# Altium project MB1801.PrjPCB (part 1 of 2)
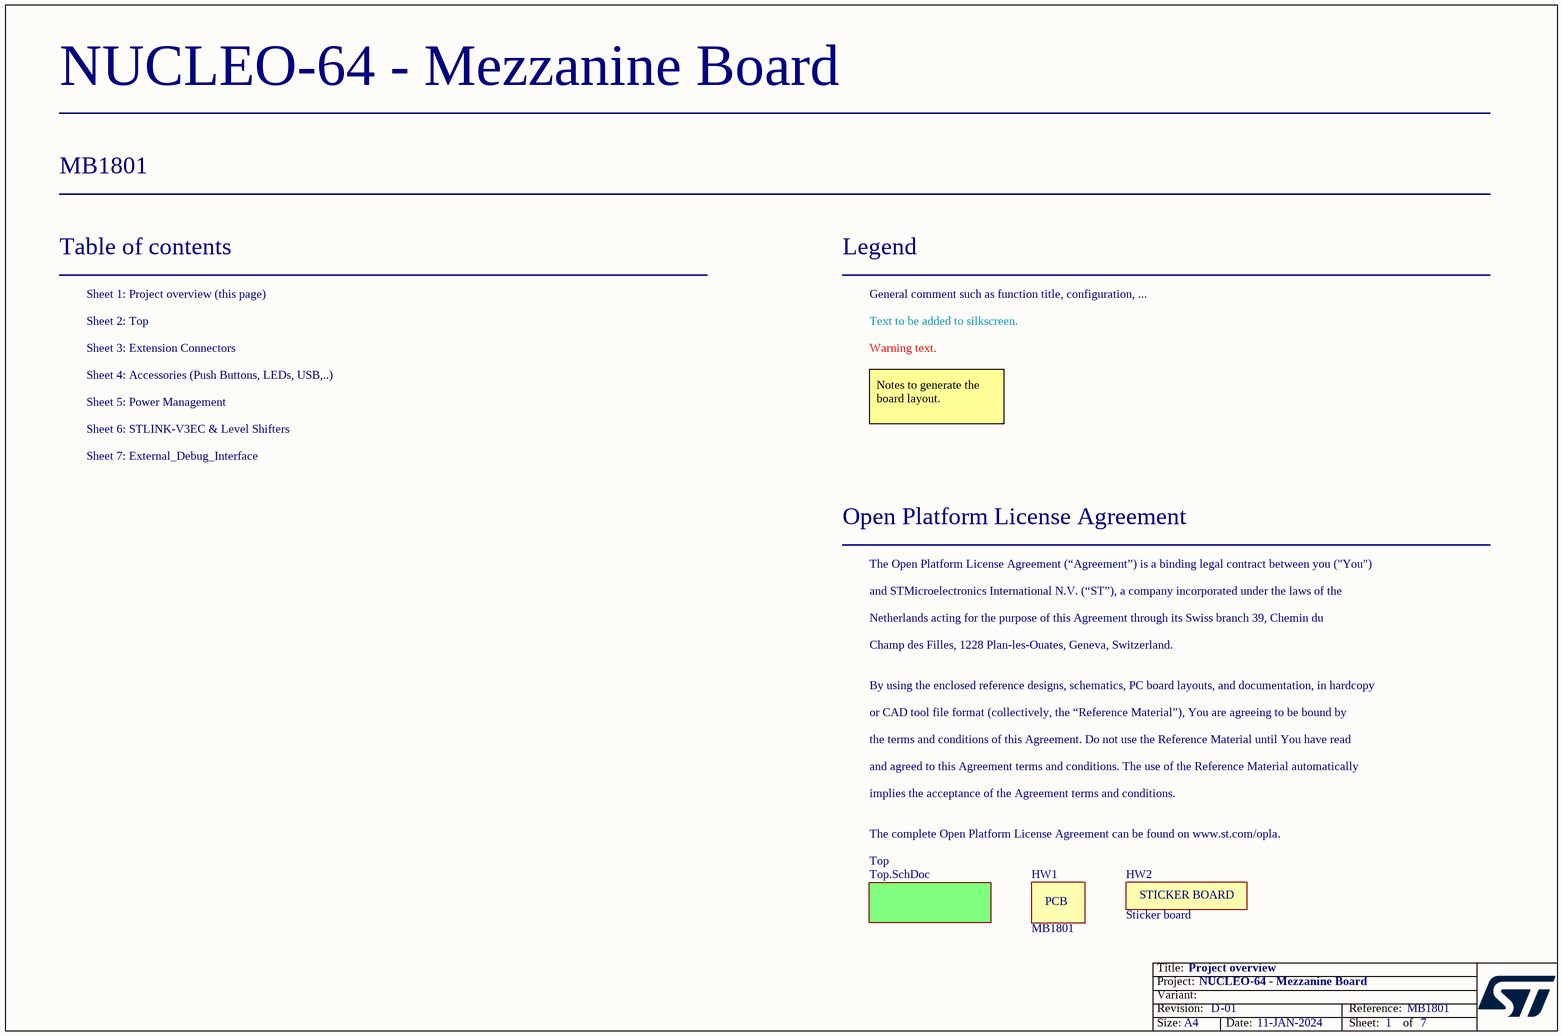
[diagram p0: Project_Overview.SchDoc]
Board_Reference: MB1801; Board_PCB_Revision: D; Board_Name: NUCLEO-64 - Mezzanine Board; Board_Document_Date: 11-JAN-2024; Board_Assembly_Revision: 01
7 sheets, 213 parts. Net scope: flat (ports and power ports of the same name join across sheets).
Board file: MB1801.PcbDoc
Sheets:
  Project_Overview.SchDoc
    Top = Top.SchDoc
      Extension Connectors = Extension_CN.SchDoc
      LEDs & Push Buttons & USB-C Connector = Accessories.SchDoc
      Power Management = Power_Management.SchDoc
      U_STlink-V3EC = STlink-V3EC.SchDoc
      U_External_Debug_Interface = External_Debug_Interface.SchDoc

## Sheet Project_Overview.SchDoc: Project overview
size A4; Date: Not used; ApprovedBy: Not used; CheckedBy: Not used; Author: Not used; CompanyName: STMicroelectronics; DrawnBy: Not used; Engineer: Not used; Organization: Not used; Address1: Not used; Address2: Not used; Address3: Not used; Address4: Not used; DocumentNumber: Not used; Revision: Not used; SheetNumber: 1; SheetTotal: 7

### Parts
HW1  value MB1801  (hidden comment: PCB_MB1801)  (no BOM)
HW2  value Sticker board  [STICKER_BOARD_25X5]  (hidden comment: STICKER_BOARD)  (no BOM)

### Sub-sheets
Top = Top.SchDoc: no entries

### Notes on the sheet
- Table of contents
- Sheet 1: Project overview (this page)
- Legend
- General comment such as function title, configuration, ...
- Sheet 2: Top
- Sheet 3: Extension Connectors
- Sheet 4: Accessories (Push Buttons, LEDs, USB,..)
- Text to be added to silkscreen.
- Warning text.
- Sheet 6: STLINK-V3EC & Level Shifters
- Sheet 5: Power Management
- Notes to generate the board layout.
- Sheet 7: External_Debug_Interface
- Open Platform License Agreement
- The Open Platform License Agreement (“Agreement”) is a binding legal contract between you ("You")
- and STMicroelectronics International N.V. (“ST”), a company incorporated under the laws of the
- Netherlands acting for the purpose of this Agreement through its Swiss branch 39, Chemin du
- Champ des Filles, 1228 Plan-les-Ouates, Geneva, Switzerland.
- By using the enclosed reference designs, schematics, PC board layouts, and documentation, in hardcopy
- or CAD tool file format (collectively, the “Reference Material”), You are agreeing to be bound by
- the terms and conditions of this Agreement. Do not use the Reference Material until You have read
- and agreed to this Agreement terms and conditions. The use of the Reference Material automatically
- implies the acceptance of the Agreement terms and conditions.
- The complete Open Platform License Agreement can be found on www.st.com/opla.

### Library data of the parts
HW1 = MCD-02707: PCB 2L2S of NUCLEO64 for MiniBoard; Part_Preference: Recommended; Manufacturer: EMS; Order_Code_RS: NA
HW2 = MCD-02190: Sticker board 25x5 mm; Part_Type: Misc; Part_Preference: Recommended

## Sheet Top.SchDoc: Top Schematic
size A4; Date: Not used; ApprovedBy: Not used; CheckedBy: Not used; Author: Not used; CompanyName: STMicroelectronics; DrawnBy: Not used; Engineer: Not used; Organization: Not used; Address1: Not used; Address2: Not used; Address3: Not used; Address4: Not used; DocumentNumber: Not used; Revision: Not used; SheetNumber: 2; SheetTotal: 7
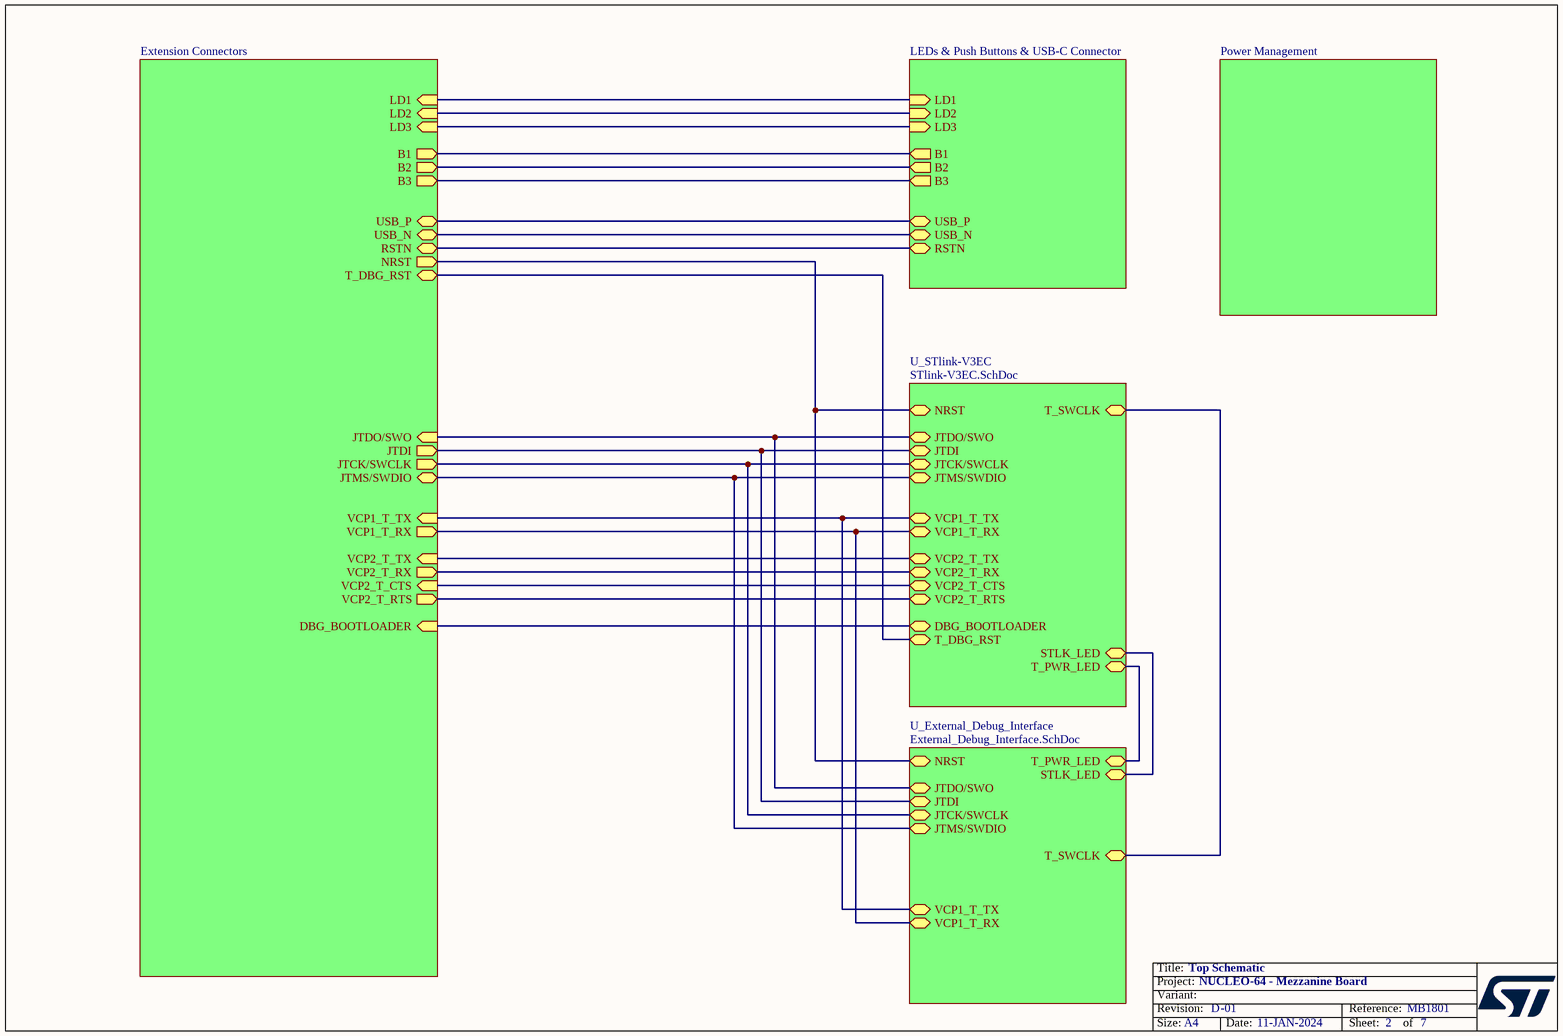
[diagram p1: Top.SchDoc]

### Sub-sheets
Extension Connectors = Extension_CN.SchDoc: JTMS/SWDIO (bidir), USB_P (bidir), USB_N (bidir), NRST (out), LD2 (in), LD3 (in), JTDI (out), B3 (out), B1 (out), JTDO/SWO (in), B2 (out), LD1 (in), DBG_BOOTLOADER (in), VCP1_T_RX (out), VCP2_T_CTS (in), VCP1_T_TX (in), VCP2_T_RX (out), VCP2_T_RTS (out), VCP2_T_TX (in), JTCK/SWCLK (out), T_DBG_RST (bidir), RSTN (bidir)
LEDs & Push Buttons & USB-C Connector = Accessories.SchDoc: LD1 (in), LD2 (in), LD3 (in), B1 (out), B2 (out), B3 (out), USB_P (bidir), USB_N (bidir), RSTN (bidir)
Power Management = Power_Management.SchDoc: no entries
U_External_Debug_Interface = External_Debug_Interface.SchDoc: JTDI (bidir), VCP1_T_TX (bidir), T_SWCLK (bidir), NRST (bidir), VCP1_T_RX (bidir), STLK_LED (bidir), T_PWR_LED (bidir), JTCK/SWCLK (bidir), JTMS/SWDIO (bidir), JTDO/SWO (bidir)
U_STlink-V3EC = STlink-V3EC.SchDoc: JTMS/SWDIO (bidir), JTDI (bidir), JTDO/SWO (bidir), NRST (bidir), DBG_BOOTLOADER (bidir), STLK_LED (bidir), VCP1_T_RX (bidir), VCP1_T_TX (bidir), T_PWR_LED (bidir), VCP2_T_RTS (bidir), VCP2_T_RX (bidir), VCP2_T_TX (bidir), T_SWCLK (bidir), VCP2_T_CTS (bidir), JTCK/SWCLK (bidir), T_DBG_RST (bidir)

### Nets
(unnamed): sheet Extension Connectors/JTMS/SWDIO, sheet U_STlink-V3EC/JTMS/SWDIO, sheet U_External_Debug_Interface/JTMS/SWDIO
(unnamed): sheet Extension Connectors/USB_P, sheet LEDs & Push Buttons & USB-C Connector/USB_P  [a separate net that carries the same name]
(unnamed): sheet Extension Connectors/USB_N, sheet LEDs & Push Buttons & USB-C Connector/USB_N  [a separate net that carries the same name]
(unnamed): sheet Extension Connectors/NRST, sheet U_STlink-V3EC/NRST, sheet U_External_Debug_Interface/NRST  [a separate net that carries the same name]
(unnamed): sheet Extension Connectors/LD2, sheet LEDs & Push Buttons & USB-C Connector/LD2  [a separate net that carries the same name]
(unnamed): sheet Extension Connectors/LD3, sheet LEDs & Push Buttons & USB-C Connector/LD3  [a separate net that carries the same name]
(unnamed): sheet Extension Connectors/JTDI, sheet U_STlink-V3EC/JTDI, sheet U_External_Debug_Interface/JTDI  [a separate net that carries the same name]
(unnamed): sheet Extension Connectors/B3, sheet LEDs & Push Buttons & USB-C Connector/B3  [a separate net that carries the same name]
(unnamed): sheet Extension Connectors/B1, sheet LEDs & Push Buttons & USB-C Connector/B1  [a separate net that carries the same name]
(unnamed): sheet Extension Connectors/JTDO/SWO, sheet U_STlink-V3EC/JTDO/SWO, sheet U_External_Debug_Interface/JTDO/SWO  [a separate net that carries the same name]
(unnamed): sheet Extension Connectors/B2, sheet LEDs & Push Buttons & USB-C Connector/B2  [a separate net that carries the same name]
(unnamed): sheet Extension Connectors/LD1, sheet LEDs & Push Buttons & USB-C Connector/LD1  [a separate net that carries the same name]
(unnamed): sheet Extension Connectors/DBG_BOOTLOADER, sheet U_STlink-V3EC/DBG_BOOTLOADER  [a separate net that carries the same name]
(unnamed): sheet Extension Connectors/VCP1_T_RX, sheet U_STlink-V3EC/VCP1_T_RX, sheet U_External_Debug_Interface/VCP1_T_RX  [a separate net that carries the same name]
(unnamed): sheet Extension Connectors/VCP2_T_CTS, sheet U_STlink-V3EC/VCP2_T_CTS  [a separate net that carries the same name]
(unnamed): sheet Extension Connectors/VCP1_T_TX, sheet U_STlink-V3EC/VCP1_T_TX, sheet U_External_Debug_Interface/VCP1_T_TX  [a separate net that carries the same name]
(unnamed): sheet Extension Connectors/VCP2_T_RX, sheet U_STlink-V3EC/VCP2_T_RX  [a separate net that carries the same name]
(unnamed): sheet Extension Connectors/VCP2_T_RTS, sheet U_STlink-V3EC/VCP2_T_RTS  [a separate net that carries the same name]
(unnamed): sheet Extension Connectors/VCP2_T_TX, sheet U_STlink-V3EC/VCP2_T_TX  [a separate net that carries the same name]
(unnamed): sheet Extension Connectors/JTCK/SWCLK, sheet U_STlink-V3EC/JTCK/SWCLK, sheet U_External_Debug_Interface/JTCK/SWCLK  [a separate net that carries the same name]
(unnamed): sheet Extension Connectors/T_DBG_RST, sheet U_STlink-V3EC/T_DBG_RST  [a separate net that carries the same name]
(unnamed): sheet Extension Connectors/RSTN, sheet LEDs & Push Buttons & USB-C Connector/RSTN  [a separate net that carries the same name]
(unnamed): sheet U_STlink-V3EC/STLK_LED, sheet U_External_Debug_Interface/STLK_LED  [a separate net that carries the same name]
(unnamed): sheet U_STlink-V3EC/T_PWR_LED, sheet U_External_Debug_Interface/T_PWR_LED  [a separate net that carries the same name]
(unnamed): sheet U_STlink-V3EC/T_SWCLK, sheet U_External_Debug_Interface/T_SWCLK  [a separate net that carries the same name]

## Sheet Extension_CN.SchDoc: Extension Connectors
size A4; Date: Not used; ApprovedBy: Not used; CheckedBy: Not used; Author: Not used; CompanyName: STMicroelectronics; DrawnBy: Not used; Engineer: Not used; Organization: Not used; Address1: Not used; Address2: Not used; Address3: Not used; Address4: Not used; DocumentNumber: Not used; Revision: Not used; SheetNumber: 3; SheetTotal: 7
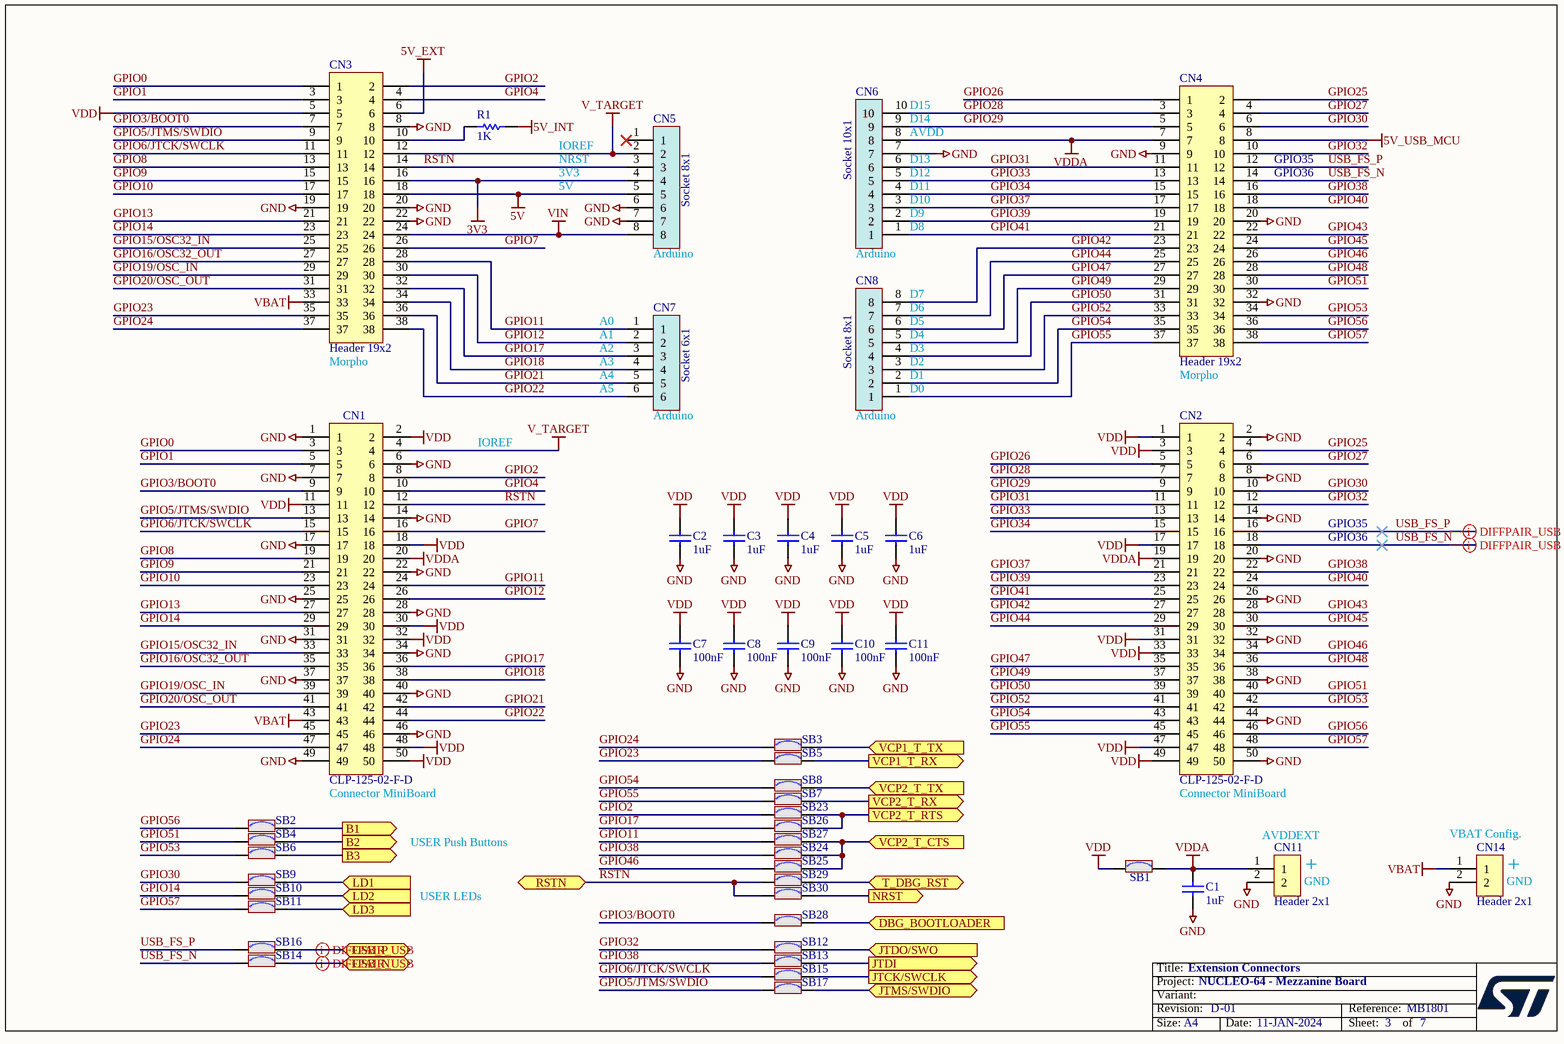
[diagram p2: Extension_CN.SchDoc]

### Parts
C1  value 1uF  [C0805_H0P85]  (hidden comment: Capacitor)
C2  value 1uF  [C0805_H0P85]  (hidden comment: Capacitor)
C3  value 1uF  [C0805_H0P85]  (hidden comment: Capacitor)
C4  value 1uF  [C0805_H0P85]  (hidden comment: Capacitor)
C5  value 1uF  [C0805_H0P85]  (hidden comment: Capacitor)
C6  value 1uF  [C0805_H0P85]  (hidden comment: Capacitor)
C7  value 100nF  [C0402]  (hidden comment: Capacitor)
C8  value 100nF  [C0402]  (hidden comment: Capacitor)
C9  value 100nF  [C0402]  (hidden comment: Capacitor)
C10  value 100nF  [C0402]  (hidden comment: Capacitor)
C11  value 100nF  [C0402]  (hidden comment: Capacitor)
CN1  CLP-125-02-F-D  [CON_SAMTEC_CLP-125-02-F-D]
CN2  CLP-125-02-F-D  [CON_SAMTEC_CLP-125-02-F-D]
CN3  Header 19x2  [CON_SAMTEC_TSW-119-09-X-D]
CN4  Header 19x2  [CON_SAMTEC_TSW-119-09-X-D]
CN5  Socket 8x1  [CON_SAMTEC_SSW-108-01-X-S]
CN6  Socket 10x1  [CON_SAMTEC_SSW-110-01-X-S]
CN7  Socket 6x1  [CON_SAMTEC_SSW-106-01-X-S]
CN8  Socket 8x1  [CON_SAMTEC_SSW-108-01-X-S]
CN11  Header 2x1  [CON_SAMTEC_TSW-102-07-G-S]
CN14  Header 2x1  [CON_SAMTEC_TSW-102-07-G-S]
R1  value 1K  [R0402]  (hidden comment: Resistor)
SB1  SB_ON  [SOLDER-BRIDGE_R0402-0R]  (value not drawn)
SB2  SB_ON  [SOLDER-BRIDGE_R0402-0R]  (value not drawn)
SB3  SB_ON  [SOLDER-BRIDGE_R0402-0R]  (value not drawn)
SB4  SB_ON  [SOLDER-BRIDGE_R0402-0R]  (value not drawn)
SB5  SB_ON  [SOLDER-BRIDGE_R0402-0R]  (value not drawn)
SB6  SB_ON  [SOLDER-BRIDGE_R0402-0R]  (value not drawn)
SB7  SB_ON  [SOLDER-BRIDGE_R0402-0R]  (value not drawn)
SB8  SB_ON  [SOLDER-BRIDGE_R0402-0R]  (value not drawn)
SB9  SB_ON  [SOLDER-BRIDGE_R0402-0R]  (value not drawn)
SB10  SB_ON  [SOLDER-BRIDGE_R0402-0R]  (value not drawn)
SB11  SB_ON  [SOLDER-BRIDGE_R0402-0R]  (value not drawn)
SB12  SB_ON  [SOLDER-BRIDGE_R0402-0R]  (value not drawn)
SB13  SB_ON  [SOLDER-BRIDGE_R0402-0R]  (value not drawn)
SB14  SB_ON  [SOLDER-BRIDGE_R0402-0R]  (value not drawn)
SB15  SB_ON  [SOLDER-BRIDGE_R0402-0R]  (value not drawn)
SB16  SB_ON  [SOLDER-BRIDGE_R0402-0R]  (value not drawn)
SB17  SB_ON  [SOLDER-BRIDGE_R0402-0R]  (value not drawn)
SB23  SB_ON  [SOLDER-BRIDGE_R0402-0R]  (value not drawn)
SB24  SB_ON  [SOLDER-BRIDGE_R0402-0R]  (value not drawn)
SB25  SB_ON  [SOLDER-BRIDGE_R0402-0R]  (value not drawn)
SB26  SB_ON  [SOLDER-BRIDGE_R0402-0R]  (value not drawn)
SB27  SB_ON  [SOLDER-BRIDGE_R0402-0R]  (value not drawn)
SB28  SB_ON  [SOLDER-BRIDGE_R0402-0R]  (value not drawn)
SB29  SB_ON  [SOLDER-BRIDGE_R0402-0R]  (value not drawn)
SB30  SB_ON  [SOLDER-BRIDGE_R0402-0R]  (value not drawn)

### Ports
B1 (out), B2 (out), B3 (out), DBG_BOOTLOADER (in), JTCK/SWCLK (out), JTDI (out), JTDO/SWO (in), JTMS/SWDIO (bidir), LD1 (in), LD2 (in), LD3 (in), NRST (out), RSTN (bidir), T_DBG_RST (bidir), USB_N (bidir), USB_P (bidir), VCP1_T_RX (out), VCP1_T_TX (in), VCP2_T_CTS (in), VCP2_T_RTS (out), VCP2_T_RX (out), VCP2_T_TX (in)

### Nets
3V3: CN3.16 CN5.4
5V: CN3.18 CN5.5
5V_EXT: CN3.6
5V_INT: R1.2
5V_USB_MCU: CN4.8
GND: C1.1 C2.1 C3.1 C4.1 C5.1 C6.1 C7.1 C8.1 C9.1 C10.1 C11.1 CN1.1 CN1.6 CN1.7 CN1.14 CN1.17 CN1.22 CN1.25 CN1.28 CN1.31 CN1.34 CN1.37 CN1.40 CN1.46 CN1.49 CN2.2 CN2.8 CN2.14 CN2.20 CN2.26 CN2.32 CN2.38 CN2.44 CN2.50 CN3.8 CN3.19 CN3.20 CN3.22 CN4.9 CN4.20 CN4.32 CN5.6 CN5.7 CN6.7 CN11.2 CN14.2
V_TARGET: CN1.4 CN3.12 CN5.2
VBAT: CN1.43 CN3.33 CN14.1
VDD: C2.2 C3.2 C4.2 C5.2 C6.2 C7.2 C8.2 C9.2 C10.2 C11.2 CN1.2 CN1.11 CN1.18 CN1.30 CN1.32 CN1.48 CN1.50 CN2.1 CN2.3 CN2.17 CN2.31 CN2.33 CN2.47 CN2.49 CN3.5 SB1.1
VDDA: C1.2 CN1.20 CN2.19 CN4.7 CN6.8 CN11.1 SB1.2
VIN: CN3.24 CN5.8
B1: SB2.2 ; port B1
B2: SB4.2 ; port B2
B3: SB6.2 ; port B3
DBG_BOOTLOADER: SB28.2 ; port DBG_BOOTLOADER
GPIO0: CN1.3 CN3.1
GPIO1: CN1.5 CN3.3
GPIO2: CN1.8 CN3.2 SB23.1
GPIO3/BOOT0: CN1.9 CN3.7 SB28.1
GPIO4: CN1.10 CN3.4
GPIO5/JTMS/SWDIO: CN1.13 CN3.9 SB17.1
GPIO6/JTCK/SWCLK: CN1.15 CN3.11 SB15.1
GPIO7: CN1.16 CN3.26
GPIO8: CN1.19 CN3.13
GPIO9: CN1.21 CN3.15
GPIO10: CN1.23 CN3.17
GPIO11: CN1.24 CN3.28 CN7.1 SB27.1
GPIO12: CN1.26 CN3.30 CN7.2
GPIO13: CN1.27 CN3.21
GPIO14: CN1.29 CN3.23 SB10.1
GPIO15/OSC32_IN: CN1.33 CN3.25
GPIO16/OSC32_OUT: CN1.35 CN3.27
GPIO17: CN1.36 CN3.32 CN7.3 SB26.1
GPIO18: CN1.38 CN3.34 CN7.4
GPIO19/OSC_IN: CN1.39 CN3.29
GPIO20/OSC_OUT: CN1.41 CN3.31
GPIO21: CN1.42 CN3.36 CN7.5
GPIO22: CN1.44 CN3.38 CN7.6
GPIO23: CN1.45 CN3.35 SB5.1
GPIO24: CN1.47 CN3.37 SB3.1
GPIO25: CN2.4 CN4.2
GPIO26: CN2.5 CN4.1
GPIO27: CN2.6 CN4.4
GPIO28: CN2.7 CN4.3 CN6.10
GPIO29: CN2.9 CN4.5 CN6.9
GPIO30: CN2.10 CN4.6 SB9.1
GPIO31: CN2.11 CN4.11 CN6.6
GPIO32: CN2.12 CN4.10 SB12.1
GPIO33: CN2.13 CN4.13 CN6.5
GPIO34: CN2.15 CN4.15 CN6.4
GPIO37: CN2.21 CN4.17 CN6.3
GPIO38: CN2.22 CN4.16 SB13.1 SB24.1
GPIO39: CN2.23 CN4.19 CN6.2
GPIO40: CN2.24 CN4.18
GPIO41: CN2.25 CN4.21 CN6.1
GPIO42: CN2.27 CN4.23 CN8.8
GPIO43: CN2.28 CN4.22
GPIO44: CN2.29 CN4.25 CN8.7
GPIO45: CN2.30 CN4.24
GPIO46: CN2.34 CN4.26 SB25.1
GPIO47: CN2.35 CN4.27 CN8.6
GPIO48: CN2.36 CN4.28
GPIO49: CN2.37 CN4.29 CN8.5
GPIO50: CN2.39 CN4.31 CN8.4
GPIO51: CN2.40 CN4.30 SB4.1
GPIO52: CN2.41 CN4.33 CN8.3
GPIO53: CN2.42 CN4.34 SB6.1
GPIO54: CN2.43 CN4.35 CN8.2 SB8.1
GPIO55: CN2.45 CN4.37 CN8.1 SB7.1
GPIO56: CN2.46 CN4.36 SB2.1
GPIO57: CN2.48 CN4.38 SB11.1
JTCK/SWCLK: SB15.2 ; port JTCK/SWCLK
JTDI: SB13.2 ; port JTDI
JTDO/SWO: SB12.2 ; port JTDO/SWO
JTMS/SWDIO: SB17.2 ; port JTMS/SWDIO
LD1: SB9.2 ; port LD1
LD2: SB10.2 ; port LD2
LD3: SB11.2 ; port LD3
NRST: SB30.2 ; port NRST
RSTN: CN1.12 CN3.14 CN5.3 SB29.1 SB30.1 ; port RSTN
T_DBG_RST: SB29.2 ; port T_DBG_RST
USB_FS_N: CN2.18 CN4.14 SB14.1
USB_FS_P: CN2.16 CN4.12 SB16.1
USB_N: SB14.2 ; port USB_N
USB_P: SB16.2 ; port USB_P
VCP1_T_RX: SB5.2 ; port VCP1_T_RX
VCP1_T_TX: SB3.2 ; port VCP1_T_TX
VCP2_T_CTS: SB24.2 SB25.2 SB27.2 ; port VCP2_T_CTS
VCP2_T_RTS: SB23.2 SB26.2 ; port VCP2_T_RTS
VCP2_T_RX: SB7.2 ; port VCP2_T_RX
VCP2_T_TX: SB8.2 ; port VCP2_T_TX
NetCN3_10: CN3.10 R1.1

Not connected (* = marked no-connect by the designer): CN5 1*

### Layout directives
differential pair; rule Impedance Constraint [Min = 85.00    Max = 95.00    ]: USB_FS_N, USB_FS_P, USB_N, USB_P

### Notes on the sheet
- (near CN6) D15
- IOREF
- NRST
- 3V3
- (near CN6) D12
- (near CN6) D13
- (near CN6) D14
- (near CN6) AVDD
- (near CN4) GPIO35
- (near CN4) GPIO36
- 5V
- (near CN6) D8
- (near CN6) D9
- (near CN6) D10
- (near CN6) D11
- (near CN5) Arduino
- (near CN6) Arduino
- (near CN8) D6
- (near CN8) D7
- (near CN3) Morpho
- (near CN7) A0
- (near CN7) A1
- (near CN7) A2
- (near CN7) A3
- (near CN7) A4
- (near CN8) D1
- (near CN8) D2
- (near CN8) D3
- (near CN8) D4
- (near CN8) D5
- (near CN4) Morpho
- (near CN7) A5
- (near CN7) Arduino
- (near CN8) Arduino
- (near CN8) D0
- GPIO35
- GPIO36
- (near CN1) Connector MiniBoard
- USER Push Buttons
- (near CN2) Connector MiniBoard
- (near CN11) AVDDEXT
- (near CN14) VBAT Config.
- USER LEDs
- (near CN11) GND
- (near CN11) +
- (near CN14) GND
- (near CN14) +

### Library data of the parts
C1-C6 = MCD-01550: Capacitor, MLCC, 1uF, 16V, X5R, +/-10%, 0805, T=0.85mm; Manufacturer_Part_Number: CC0805KRX5R7BB105; Manufacturer: YAGEO; Part_Preference: Recommended; Component_Country_Of_Origin: China
C7-C11 = MCD-02355: Capacitor, MLCC, 100nF, 25V, X7R, +/-10%, 0402, T=0.5mm; Part_Preference: Recommended; Manufacturer: WALSIN; Manufacturer_Part_Number: 0402B104K250CT; Order_Code_RS: 176-3114; Component_Country_Of_Origin: Unknown
CN1 CN2 = MCD-02705: Socket, 25x2, 1.27mm, VR, SMD, T=2.29mm; Part_Type: Connector; Part_Preference: Recommended; Manufacturer: SAMTEC; Value: Socket 25x2; Order_Code_RS: 180-3642; Component_Country_Of_Origin: USA; ShowFields: YES; ID: 4811
CN3 CN4 = MCD-00213: Header, 19x2, 2.54mm, VR, TH, T=5.84mm/10.16mm; Part_Type: Connector; Part_Preference: Recommended; Manufacturer: SAMTEC; Manufacturer_Part_Number: TSW-119-09-G-D; Component_Country_Of_Origin: China, Costa Rica, Malaysia, United States, Vietnam
CN5 CN8 = MCD-01743: Socket, 8x1, 2.54mm, VR, TH, T=8.51/2.64mm; Part_Type: Connector; Part_Preference: Recommended; Manufacturer: SAMTEC; Manufacturer_Part_Number: SSW-108-01-G-S; Order_Code_RS: 765-5698; Component_Country_Of_Origin: China, Costa Rica, Malaysia, United States, Vietnam
CN6 = MCD-02080: Socket, 10x1, 2.54mm, VR, TH, T=8.51/2.64mm; Part_Type: Connector; Part_Preference: Recommended; Manufacturer: SAMTEC; Manufacturer_Part_Number: SSW-110-01-G-S; Order_Code_RS: 765-5736; Component_Country_Of_Origin: China, Costa Rica, Malaysia, United States, Vietnam
CN7 = MCD-02079: Socket, 6x1, 2.54mm, VR, TH, T=8.51/2.64mm; Part_Type: Connector; Part_Preference: Recommended; Manufacturer: SAMTEC; Manufacturer_Part_Number: SSW-106-01-G-S; Order_Code_RS: 765-5666; Component_Country_Of_Origin: China, Costa Rica, Malaysia, United States, Vietnam
CN11 CN14 = MCD-00032: Header, 2x1, 2.54mm, VR, TH, T=5.84mm/2.54mm; Part_Type: Connector; Part_Preference: Recommended; Manufacturer: SAMTEC; Manufacturer_Part_Number: TSW-102-07-G-S; Order_Code_RS: 155-5312; Component_Country_Of_Origin: China, Costa Rica, Malaysia, United States, Vietnam
R1 = MCD-00061: Resistor, 1K, 0402, +/-1%,1/16W; Part_Preference: Recommended; Manufacturer: YAGEO; Manufacturer_Part_Number: RC0402FR-071KL; Component_Country_Of_Origin: China
SB1-SB17 SB23-SB30 = MCD-01618: Solder Bridge 0402 ON; Part_Type: Misc; Part_Preference: Recommended; Manufacturer: YAGEO; Manufacturer_Part_Number: RC0402JR-070RL; Order_Code_RS: 618-5804; Component_Country_Of_Origin: China

## Sheet Accessories.SchDoc: LEDs & Push Buttons & USB-C Connector
size A4; Date: Not used; ApprovedBy: Not used; CheckedBy: Not used; Author: Not used; CompanyName: STMicroelectronics; DrawnBy: Not used; Engineer: Not used; Organization: Not used; Address1: Not used; Address2: Not used; Address3: Not used; Address4: Not used; DocumentNumber: Not used; Revision: Not used; SheetNumber: 4; SheetTotal: 7
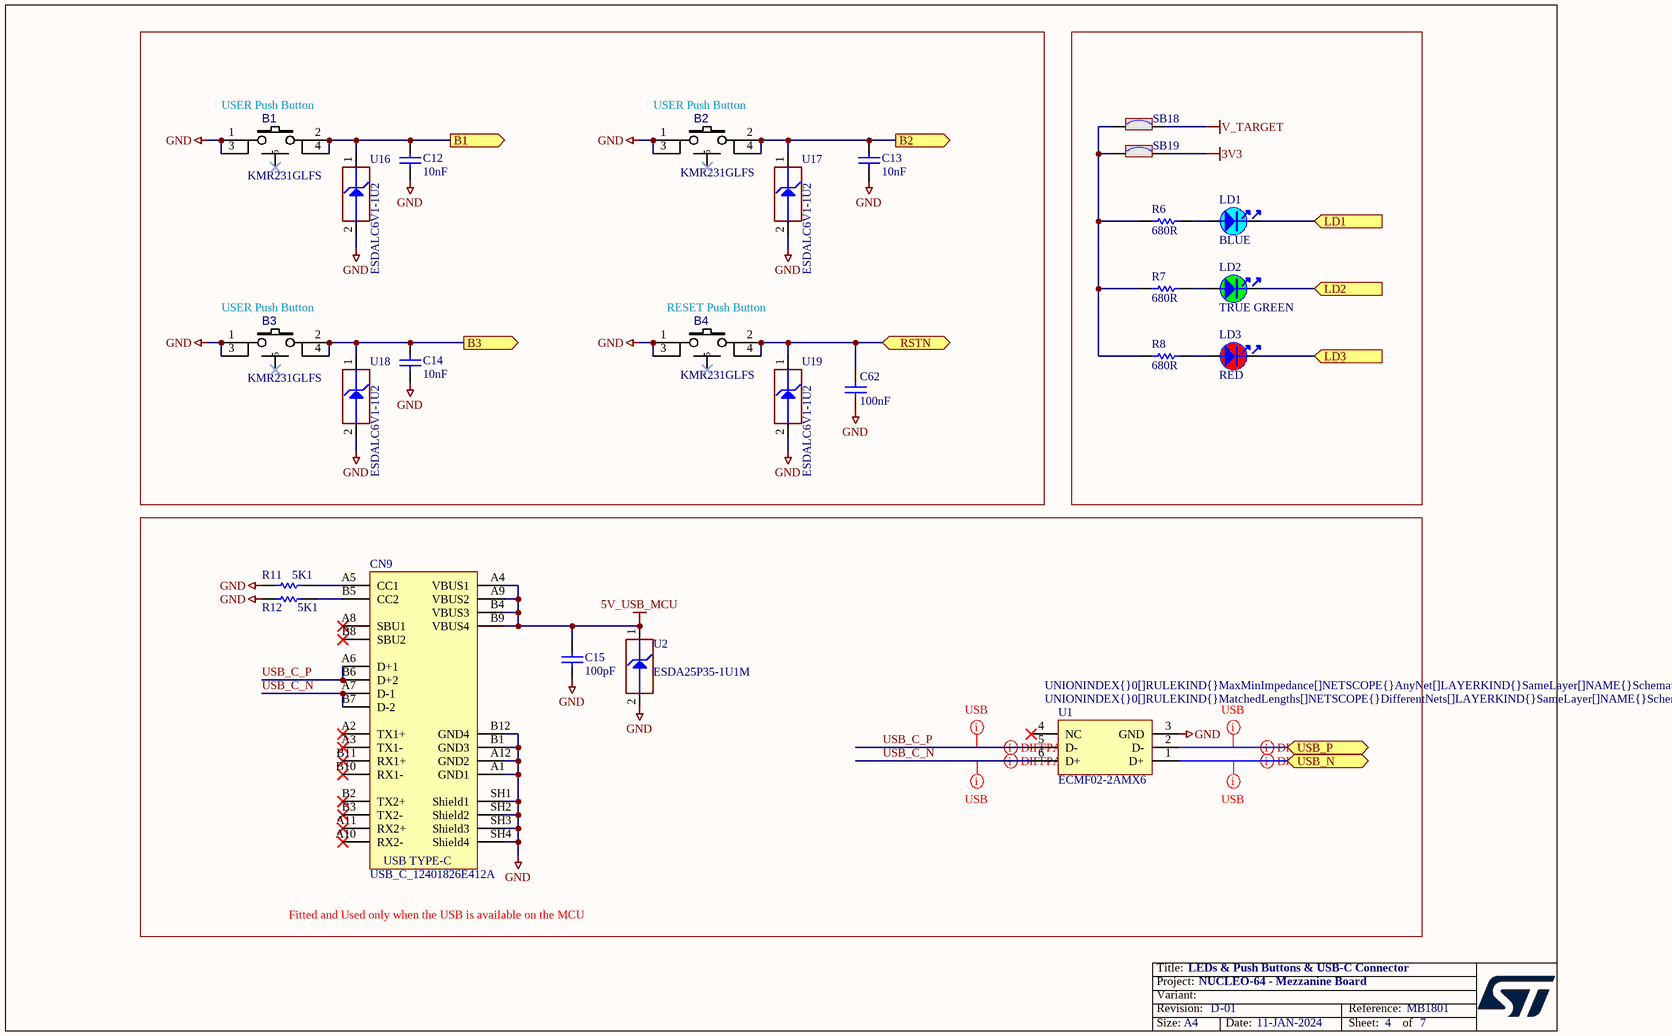
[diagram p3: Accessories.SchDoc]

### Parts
B1  value KMR231GLFS  [SWI_C&K_Y78B23110FP__ITT_KMR231GLFS]  (hidden comment: SW-PUSH-CMS_KMR2_BLACK)
B2  value KMR231GLFS  [SWI_C&K_Y78B23110FP__ITT_KMR231GLFS]  (hidden comment: SW-PUSH-CMS_KMR2_BLACK)
B3  value KMR231GLFS  [SWI_C&K_Y78B23110FP__ITT_KMR231GLFS]  (hidden comment: SW-PUSH-CMS_KMR2_BLACK)
B4  value KMR231GLFS  [SWI_C&K_Y78B23110FP__ITT_KMR231GLFS]  (hidden comment: SW-PUSH-CMS_KMR2_BLACK)
C12  value 10nF  [C0402]  (hidden comment: Capacitor)
C13  value 10nF  [C0402]  (hidden comment: Capacitor)
C14  value 10nF  [C0402]  (hidden comment: Capacitor)
C15  value 100pF  [C0402]  (hidden comment: Capacitor)
C62  value 100nF  [C0402]  (hidden comment: Capacitor)
CN9  value USB_C_12401826E412A  [CON_USB-TYPEC_AMPHENOL_12401826E412A]  (hidden comment: USB_TYPE_C_Receptacle)
LD1  value BLUE  [LED_0603_VISHAY_VLMB1300-GS08_BLUE_1A2K_H0P8]  (hidden comment: LED_blue)
LD2  value TRUE GREEN  [LED_0603_VISHAY_VLMTG1300-GS08_GREEN_1A2K_H0P8]  (hidden comment: LED_green)
LD3  value RED  [LED_0603_VISHAY_VLMS1300-GS08_RED_1A2K_H0P8]  (hidden comment: LED_red)
R6  value 680R  [R0402]  (hidden comment: Resistor)
R7  value 680R  [R0402]  (hidden comment: Resistor)
R8  value 680R  [R0402]  (hidden comment: Resistor)
R11  value 5K1  [R0402]  (hidden comment: Resistor)
R12  value 5K1  [R0402]  (hidden comment: Resistor)
SB18  SB_ON  [SOLDER-BRIDGE_R0402-0R]  (value not drawn)
SB19  SB_ON  [SOLDER-BRIDGE_R0402-0R]  (value not drawn)
U1  ECMF02-2AMX6  [ESD_QFN-6L_1P7X1P5_P050]
U2  value ESDA25P35-1U1M  [ESD_QFN1610_2N_1K_2A]  (hidden comment: ESD-TRANSIL)
U16  value ESDALC6V1-1U2  [ESD_ST0201]  (hidden comment: ESD-TRANSIL)
U17  value ESDALC6V1-1U2  [ESD_ST0201]  (hidden comment: ESD-TRANSIL)
U18  value ESDALC6V1-1U2  [ESD_ST0201]  (hidden comment: ESD-TRANSIL)
U19  value ESDALC6V1-1U2  [ESD_ST0201]  (hidden comment: ESD-TRANSIL)

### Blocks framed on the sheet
Fitted and Used only when the USB is available on the MCU: C15 CN9 R11 R12 U1 U2

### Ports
B1 (out), B2 (out), B3 (out), LD1 (in), LD2 (in), LD3 (in), RSTN (bidir), USB_N (bidir), USB_P (bidir)

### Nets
3V3: SB19.2
5V_USB_MCU: C15.2 CN9.A4(VBUS1) CN9.A9(VBUS2) CN9.B4(VBUS3) CN9.B9(VBUS4) U2.1(IO1)
GND: B1.1 B1.3 B2.1 B2.3 B3.1 B3.3 B4.1 B4.3 C12.1 C13.1 C14.1 C15.1 C62.2 CN9.A1(GND1) CN9.A12(GND2) CN9.B1(GND3) CN9.B12(GND4) CN9.SH1(Shield1) CN9.SH2(Shield2) CN9.SH3(Shield3) CN9.SH4(Shield4) R11.1 R12.1 U1.3(GND) U2.2(GND) U16.2(GND) U17.2(GND) U18.2(GND) U19.2(GND)
V_TARGET: SB18.2
B1: B1.2 B1.4 C12.2 U16.1(IO1) ; port B1
B2: B2.2 B2.4 C13.2 U17.1(IO1) ; port B2
B3: B3.2 B3.4 C14.2 U18.1(IO1) ; port B3
LD1: LD1.2 ; port LD1
LD2: LD2.2 ; port LD2
LD3: LD3.2 ; port LD3
RSTN: B4.2 B4.4 C62.1 U19.1(IO1) ; port RSTN
USB_C_N: CN9.A7(D-1) CN9.B7(D-2) U1.6(D+)
USB_C_P: CN9.A6(D+1) CN9.B6(D+2) U1.5(D-)
USB_N: U1.1(D+) ; port USB_N
USB_P: U1.2(D-) ; port USB_P
NetCN9_A5: CN9.A5(CC1) R11.2
NetCN9_B5: CN9.B5(CC2) R12.2
NetLD1_1: LD1.1 R6.2
NetLD2_1: LD2.1 R7.2
NetLD3_1: LD3.1 R8.2
NetR6_1: R6.1 R7.1 R8.1 SB18.1 SB19.1

Not connected (* = marked no-connect by the designer): B1 5*; B2 5*; B3 5*; B4 5*; CN9 A2(TX1+)* A3(TX1-)* A8(SBU1)* A10(RX2-)* A11(RX2+)* B2(TX2+)* B3(TX2-)* B8(SBU2)* B10(RX1-)* B11(RX1+)*; U1 4(NC)*

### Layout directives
differential pair; rule Impedance Constraint [Min = 85.00    Max = 95.00    ]: USB_C_N, USB_C_P, USB_N, USB_P
rule Undefined; rule Matched Net Lengths [Tolerance = 2mm]; rule Impedance Constraint [Min = 85.00    Max = 95.00    ]: USB_C_N, USB_C_P, USB_N, USB_P

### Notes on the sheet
- (near B1) USER Push Button
- (near B2) USER Push Button
- (near B3) USER Push Button
- (near B4) RESET Push Button

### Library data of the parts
B1-B4 = MCD-01485: Microminiature Tact Switch for SMT - KMR 2 Series - 1.9 mm height; Part_Type: Misc; Manufacturer: C&K; Part_Preference: Recommended; Component_Country_Of_Origin: France
C12-C14 = MCD-02198: Capacitor, MLCC, 10nF, 50V, X7R, +/-10%, 0402, T=0.5mm; Part_Preference: Recommended; Manufacturer: YAGEO; Manufacturer_Part_Number: CC0402KRX7R9BB103; Order_Code_RS: 6169644; Component_Country_Of_Origin: China
C15 = MCD-00205: Capacitor, MLCC, 100pF, 50V, NPO, +/-5%, 0402, T=0.5mm; Manufacturer_Part_Number: CC0402JRNPO9BN101; Manufacturer: YAGEO; Part_Preference: Recommended; Component_Country_Of_Origin: China
C62 = MCD-00006: Capacitor, MLCC, 100nF, 16V, X7R, 10%, 0402, T=0.5mm; Manufacturer_Part_Number: CC0402KRX7R7BB104; Manufacturer: YAGEO; Alternate_Manufacturer_Part_Number: GCM155R71C104KA55D; Alternate_Manufacturer: MURATA; Provided_By: SUBCO
CN9 = MCD-03232: USB_TypeC, 24 pins, RA, SMD, T=2.96mm; Part_Type: Connector; Part_Preference: Recommended; Manufacturer: AMPHENOL ICC; Manufacturer_Part_Number: 12401826E412A; Component_Country_Of_Origin: China°; ShowFields: YES; ID: 5348
LD1 = MCD-00584: LED Blue, 0603 SMD, 3.3 V Forward Voltage; Part_Type: Display; Manufacturer_Part_Number: VLMB1300-GS08; Manufacturer: VISHAY; Part_Preference: Recommended; Order_Code_RS: 7730430; Component_Country_Of_Origin: China
LD2 = MCD-00589: LED Green, 0603 SMD, Fw Voltage = 2.8V - 3.6V; Part_Type: Display; Manufacturer_Part_Number: VLMTG1300-GS08; Manufacturer: VISHAY; Part_Preference: Recommended; Order_Code_RS: 7730452; Component_Country_Of_Origin: China
LD3 = MCD-00587: LED Red, 0603 SMD, 2V Forward Voltage; Part_Type: Display; Manufacturer_Part_Number: VLMS1300-GS08; Manufacturer: VISHAY; Part_Preference: Recommended; Alternate_Internal_Part_Number: MCD-02401; Component_Country_Of_Origin: China
R6-R8 = MCD-00507: Resistor, 680R, 0402, +/-1%, 1/16W; Manufacturer_Part_Number: RC0402FR-07680RL; Manufacturer: YAGEO; Part_Preference: Recommended; Component_Country_Of_Origin: China
R11 R12 = MCD-00333: Resistor, 5K1, 0402, +/-1%, 1/16W; Manufacturer_Part_Number: RC0402FR-075K1L; Manufacturer: YAGEO; Part_Preference: Recommended; Component_Country_Of_Origin: China
SB18 SB19 = MCD-01618: as SB1 on sheet Extension_CN
U1 = MCD-00649: Common mode filter with ESD protection for USB 2.0 interface; Part_Type: Diode; Manufacturer: STMICROELECTRONICS; BMS_Part_Number: 9151138; Part_Preference: Recommended; Manufacturer_HQ_COO: EU; Component_Country_Of_Origin: China
U2 = MCD-01207: High power Transient voltage suppressor:25V/35A EOS and ESD transients protection.; Part_Type: Diode; Manufacturer: STMICROELECTRONICS; BMS_Part_Number: 9179045; Part_Preference: Recommended; Manufacturer_HQ_COO: EU; Component_Country_Of_Origin: China
U16-U19 = MCD-00170: ESD protection 6V1; BMS_Part_Number: 9151132; Part_Type: Diode; Part_Preference: Recommended; Manufacturer: STMICROELECTRONICS; Manufacturer_HQ_COO: EU; Component_Country_Of_Origin: China; ShowFields: YES; ID: 2696

## Sheet Power_Management.SchDoc: Power Management
size A4; Date: Not used; ApprovedBy: Not used; CheckedBy: Not used; Author: Not used; CompanyName: STMicroelectronics; DrawnBy: Not used; Engineer: Not used; Organization: Not used; Address1: Not used; Address2: Not used; Address3: Not used; Address4: Not used; DocumentNumber: Not used; Revision: Not used; SheetNumber: 5; SheetTotal: 7
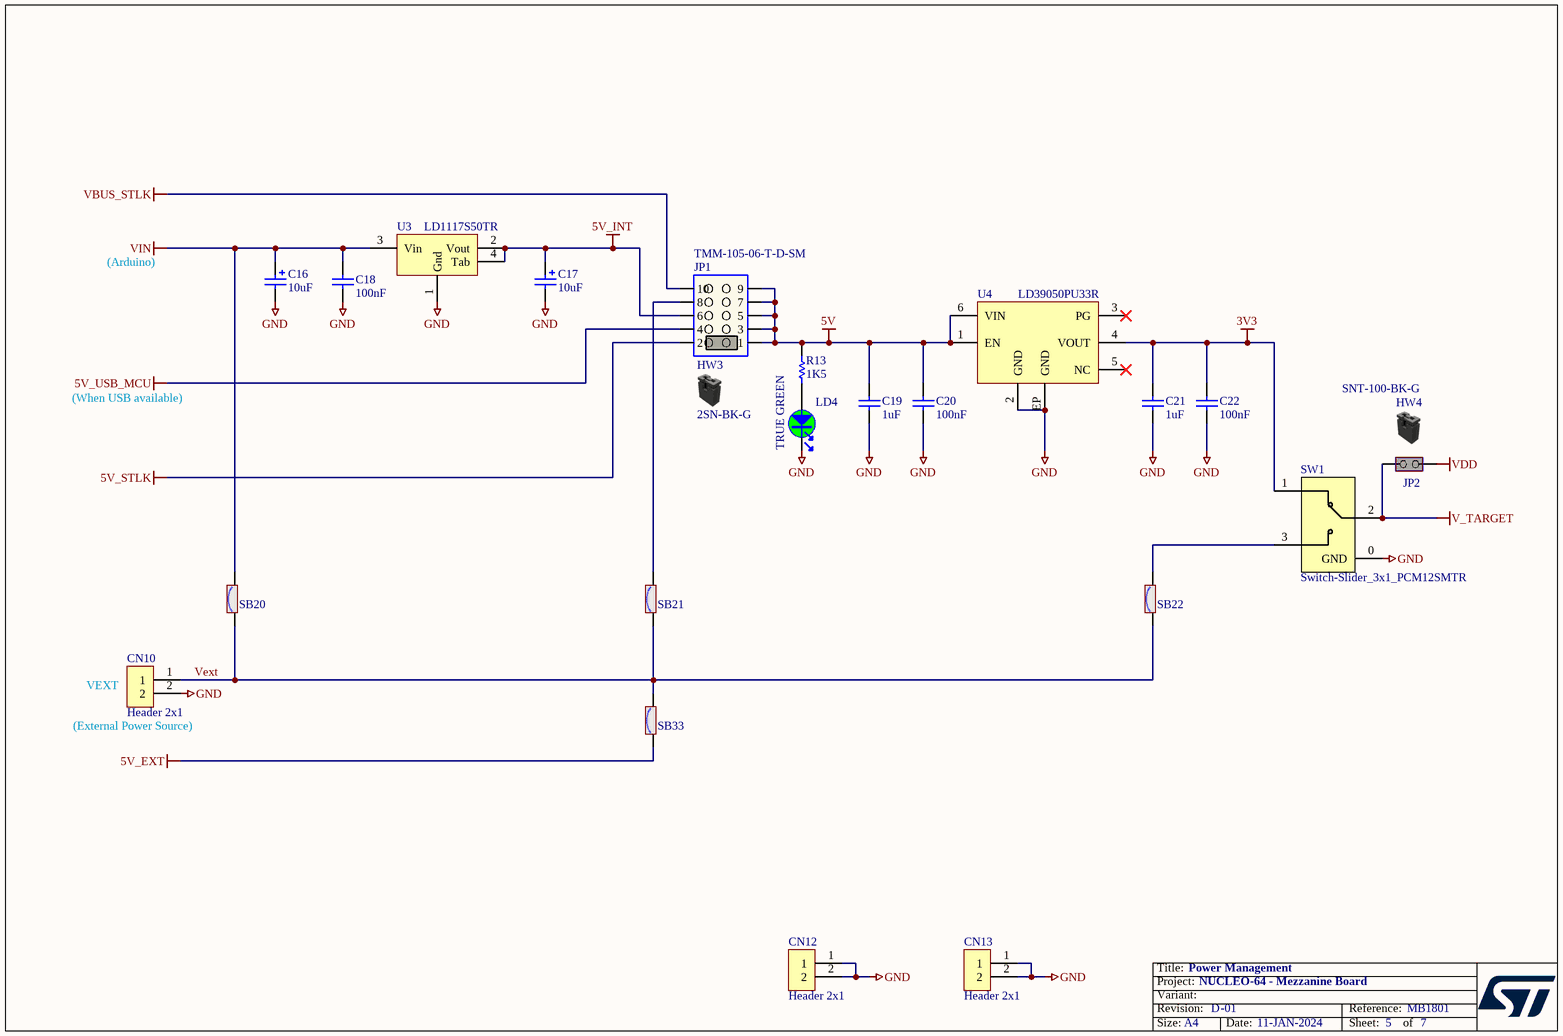
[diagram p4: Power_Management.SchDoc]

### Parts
C16  value 10uF  [CPOL_TAJ-B_1210_H210]  (hidden comment: Cap_POL_TANA)
C17  value 10uF  [CPOL_TAJ-B_1210_H210]  (hidden comment: Cap_POL_TANA)
C18  value 100nF  [C0402]  (hidden comment: Capacitor)
C19  value 1uF  [C0805_H0P85]  (hidden comment: Capacitor)
C20  value 100nF  [C0402]  (hidden comment: Capacitor)
C21  value 1uF  [C0805_H0P85]  (hidden comment: Capacitor)
C22  value 100nF  [C0402]  (hidden comment: Capacitor)
CN10  Header 2x1  [CON_SAMTEC_TSW-102-07-G-S]
CN12  Header 2x1  [CON_SAMTEC_TSW-102-07-G-S]
CN13  Header 2x1  [CON_SAMTEC_TSW-102-07-G-S]
HW3  2SN-BK-G
HW4  value SNT-100-BK-G  (hidden comment: Shunt Black 2.54mm)  (mechanical)
JP1  value TMM-105-06-T-D-SM  [CON_SAMTEC_TMM-105-06-T-D-SM]  (hidden comment: Jumper 5 Positions)
JP2  Jumper_Header 2x1 Fitted  [CON_SAMTEC_TSW-102-07-G-S]  (value not drawn)
LD4  value TRUE GREEN  [LED_0603_VISHAY_VLMTG1300-GS08_GREEN_1A2K_H0P8]  (hidden comment: LED_green)
R13  value 1K5  [R0402]  (hidden comment: Resistor)
SB20  SB_ON  [SOLDER-BRIDGE_R0402-0R]  (value not drawn)
SB21  SB_ON  [SOLDER-BRIDGE_R0402-0R]  (value not drawn)
SB22  SB_ON  [SOLDER-BRIDGE_R0402-0R]  (value not drawn)
SB33  SB_ON  [SOLDER-BRIDGE_R0402-0R]  (value not drawn)
SW1  value Switch-Slider_3x1_PCM12SMTR  [SWI_SPDT-RA_TE-CONNECTIVITY_MLL1200S_1P2T]  (hidden comment: SW_MECA)
U3  LD1117S50TR  [REG_SOT223-TAB]
U4  LD39050PU33R  [ICC_DFN6-EPAD_3X3_P095]

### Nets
3V3: C21.2 C22.2 SW1.1 U4.4(VOUT)
5V: C19.2 C20.2 JP1.1 JP1.3 JP1.5 JP1.7 JP1.9 R13.2 U4.1(EN) U4.6(VIN)
5V_EXT: SB33.1
5V_INT: C17.1 JP1.6 U3.2(Vout) U3.4(Tab)
5V_STLK: JP1.2
5V_USB_MCU: JP1.4
GND: C16.2 C17.2 C18.1 C19.1 C20.1 C21.1 C22.1 CN10.2 CN12.1 CN12.2 CN13.1 CN13.2 LD4.2 SW1.0(GND) U3.1(Gnd) U4.2(GND) U4.EP(GND)
V_TARGET: JP2.1(COMMON) SW1.2
VBUS_STLK: JP1.10
VDD: JP2.2(NO)
VIN: C16.1 C18.2 SB20.2 U3.3(Vin)
Vext: CN10.1 SB20.1 SB21.1 SB22.1 SB33.2
NetJP1_8: JP1.8 SB21.2
NetLD4_1: LD4.1 R13.1
NetSB22_2: SB22.2 SW1.3

Not connected (* = marked no-connect by the designer): U4 3(PG)* 5(NC)*

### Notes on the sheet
- (Arduino)
- (When USB available)
- (near CN10) VEXT
- (near CN10) (External Power Source)

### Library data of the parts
C16 C17 = MCD-00324: Capacitor, Tantalum, 10uF, 25V, 2R5, +/-10%, Type_B (3528 metric), T=1.9mm; Manufacturer_Part_Number: TAJB106K025RNJ; Manufacturer: AVX; Part_Preference: Recommended; Order_Code_RS: 136-0159; Component_Country_Of_Origin: El Salvador
C18 C20 C22 = MCD-02355: as C7 on sheet Extension_CN
C19 C21 = MCD-01550: as C1 on sheet Extension_CN
CN10 CN12 CN13 = MCD-00032: as CN11 on sheet Extension_CN
HW3 = MCD-03319: Shunt, 2,00mm, black; Part_Type: Connector; Part_Preference: Recommended; Manufacturer: SAMTEC; Full_Alternate_Internal_Part_Number: CHERNG-WEEI_CMJ-20AB; Order_code_RS: 159-3178; ShowFields: YES; ID: 5435
HW4 = MCD-00043: SHUNT 2.54mm BLACK; Part_Type: Misc; Manufacturer: SAMTEC; Part_Preference: Recommended; Alternate_Internal_Part_Number: MCD-02388; Component_Country_Of_Origin: China, Costa Rica, Malaysia, United States, Vietnam
JP1 = MCD-03317: Header, 10x2, 2,00mm, h=7,04mm, VR, SMD; Part_Type: Connector; Part_Preference: Recommended; Manufacturer: SAMTEC; Full_Alternate_Internal_Part_Number: CHERNG-WEEI_P401-MG4GN-0404-10-R; ShowFields: YES; ID: 5433
JP2 = MCD-01904: Header, 2x1, 2.54mm, VR, TH, T=5.84mm/2.54mm; Part_Type: Connector; Manufacturer_Part_Number: TSW-102-07-G-S; Manufacturer: SAMTEC; Part_Preference: Recommended; Order_Code_RS: 155-7981; Component_Country_Of_Origin: China, Costa Rica, Malaysia, United States, Vietnam
LD4 = MCD-00589: as LD2 on sheet Accessories
R13 = MCD-00068: Resistor, 1K5, 0402, +/-1%, 1/16W; Part_Preference: Recommended; Manufacturer: YAGEO; Manufacturer_Part_Number: RC0402FR-071K5L; Component_Country_Of_Origin: China; ShowFields: YES; ID: 2524
SB20-SB22 SB33 = MCD-01618: as SB1 on sheet Extension_CN
SW1 = MCD-03571: Slide switch, 3x1, 1.5mm, RA, SMT, T=1.65mm; Part_Type: Connector; Part_Preference: Recommended; Manufacturer: C&K; Manufacturer_Part_Number: PCM12SMTR; Order_Code_RS: 793-1721; ShowFields: YES; ID: 5687
U3 = MCD-00088: IC REG LDO 5V 0.8A SOT223; Manufacturer: STMICROELECTRONICS; BMS_Part_Number: 9176133; Part_Preference: Recommended; Manufacturer_HQ_COO: EU; Component_Country_Of_Origin: China
U4 = MCD-00215: Low quiescent current and low noise voltage regulators; Part_Type: IC; Manufacturer: STMICROELECTRONICS; BMS_Part_Number: 9176126; Part_Preference: Recommended; Manufacturer_HQ_COO: EU; Component_Country_Of_Origin: Malaysia

## Sheet STlink-V3EC.SchDoc: STLINK-V3EC
size A3; Date: Not used; ApprovedBy: Not used; CheckedBy: Not used; Author: Not used; CompanyName: STMicroelectronics; DrawnBy: Not used; Engineer: Not used; Organization: Not used; Address1: Not used; Address2: Not used; Address3: Not used; Address4: Not used; DocumentNumber: Not used; Revision: Not used; SheetNumber: 6; SheetTotal: 7
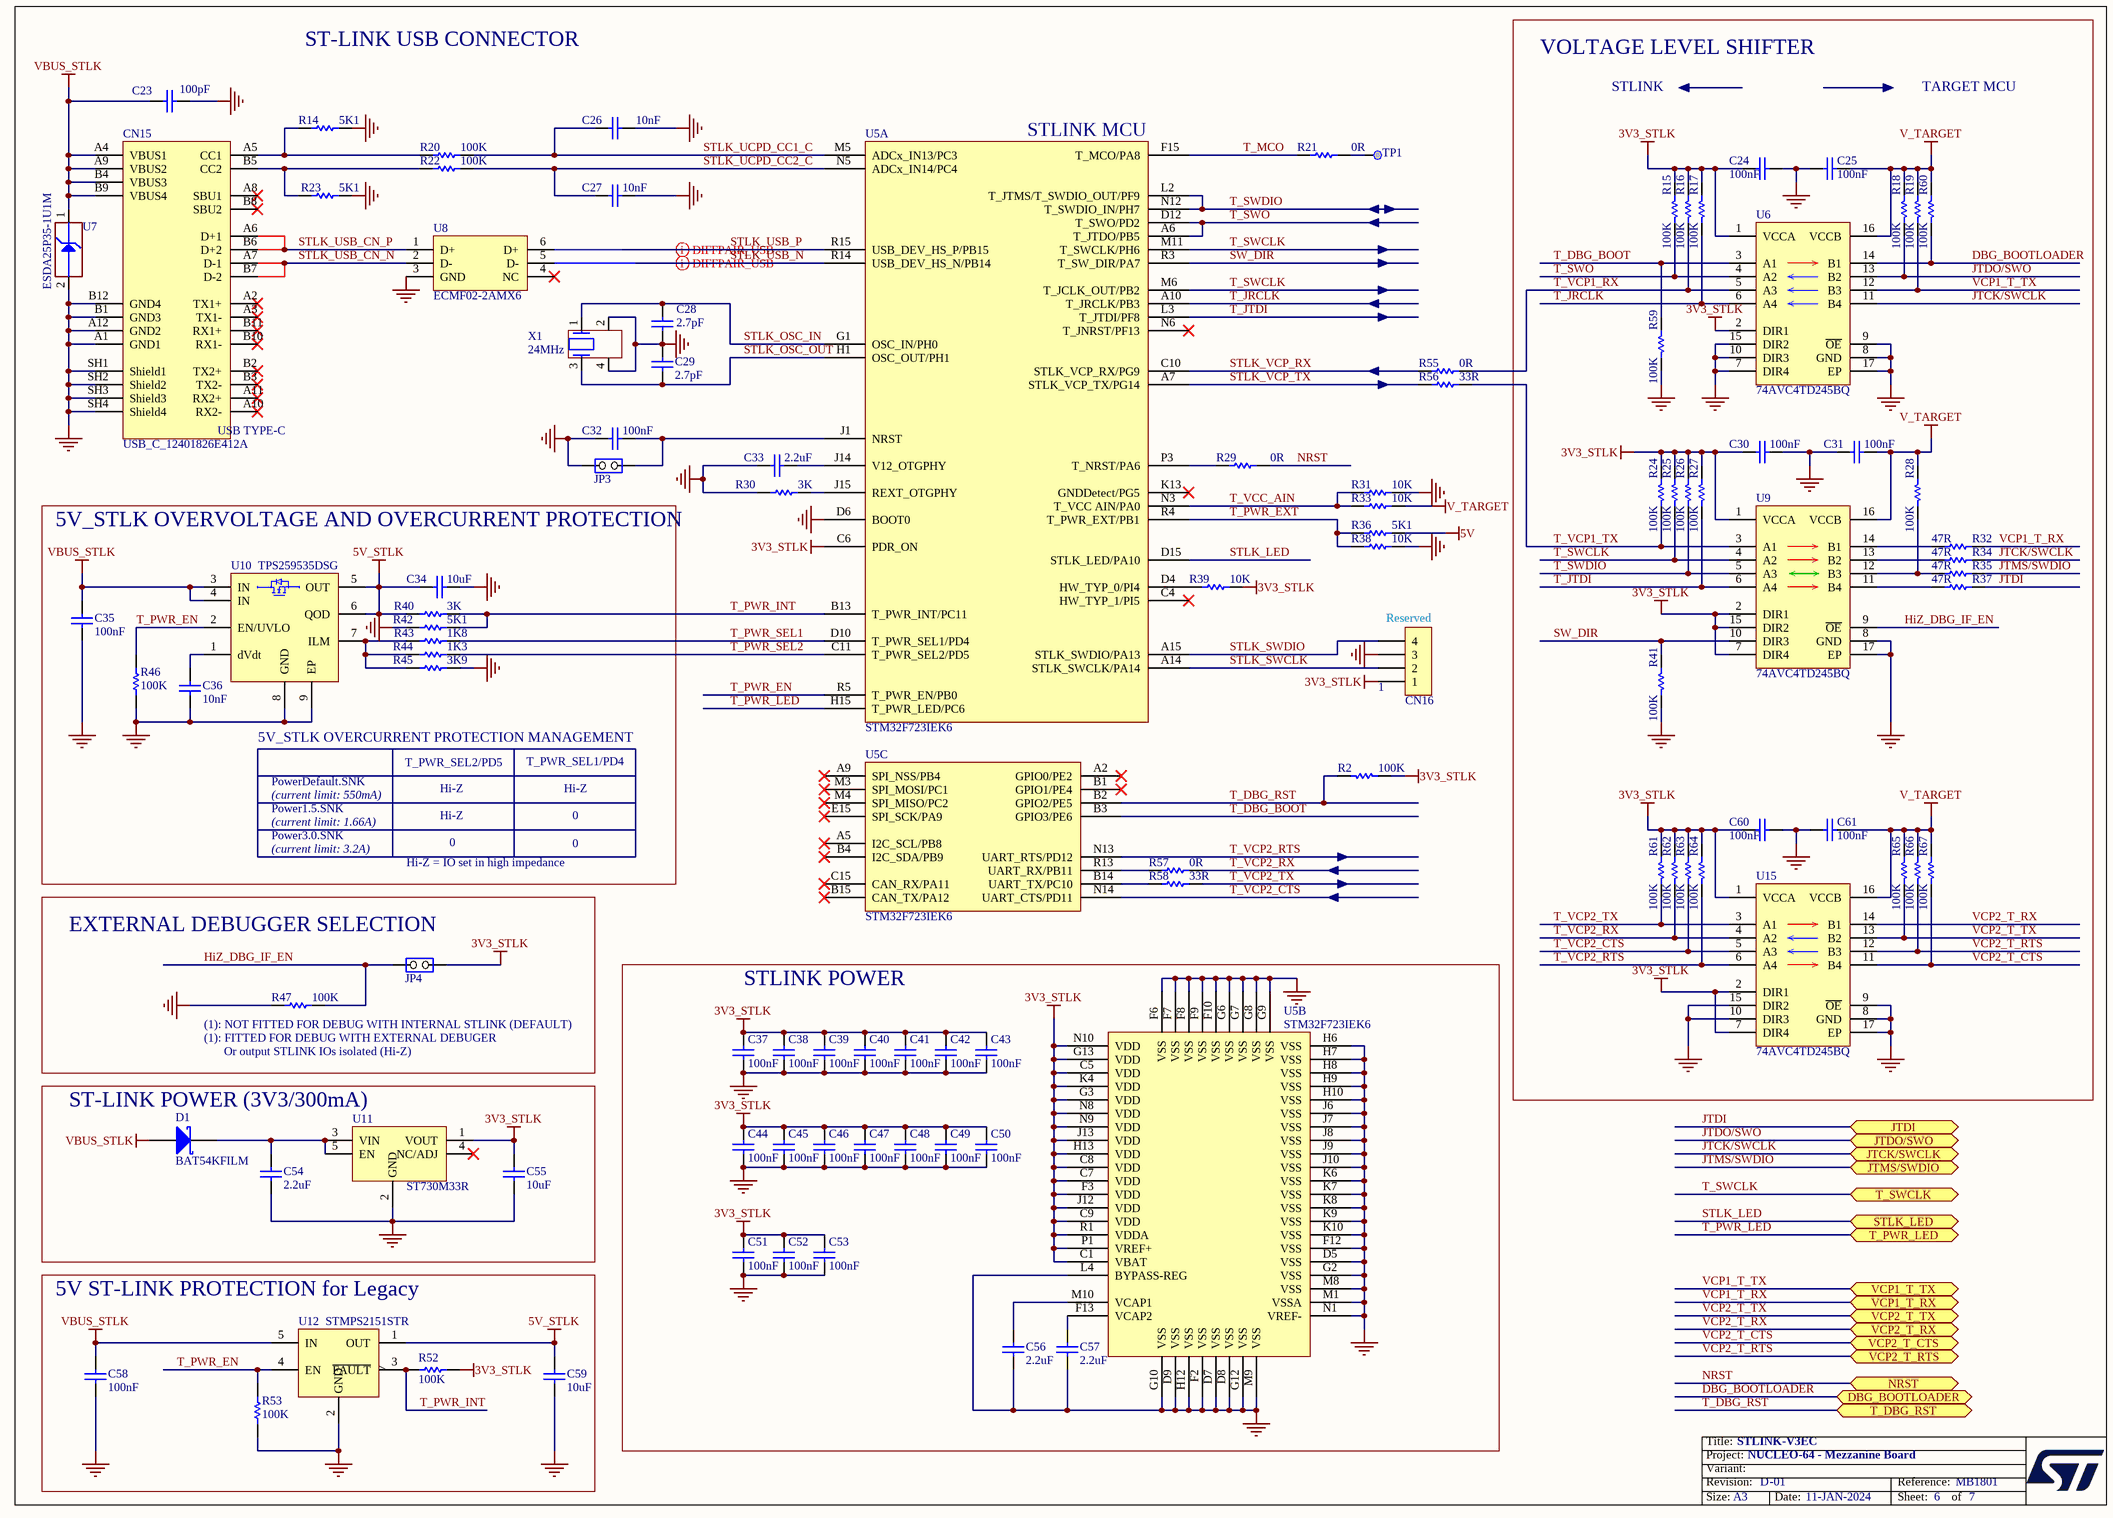
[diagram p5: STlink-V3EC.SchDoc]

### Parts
C23  value 100pF  [C0402]  (hidden comment: Capacitor)
C24  value 100nF  [C0402]  (hidden comment: Capacitor)
C25  value 100nF  [C0402]  (hidden comment: Capacitor)
C26  value 10nF  [C0402]  (hidden comment: Capacitor)
C27  value 10nF  [C0402]  (hidden comment: Capacitor)
C28  value 2.7pF  [C0402]  (hidden comment: Capacitor)
C29  value 2.7pF  [C0402]  (hidden comment: Capacitor)
C30  value 100nF  [C0402]  (hidden comment: Capacitor)
C31  value 100nF  [C0402]  (hidden comment: Capacitor)
C32  value 100nF  [C0402]  (hidden comment: Capacitor)
C33  value 2.2uF  [C0402]  (hidden comment: Capacitor)
C34  value 10uF  [C0603]  (hidden comment: Capacitor)
C35  value 100nF  [C0402]  (hidden comment: Capacitor)
C36  value 10nF  [C0402]  (hidden comment: Capacitor)
C37  value 100nF  [C0402]  (hidden comment: Capacitor)
C38  value 100nF  [C0402]  (hidden comment: Capacitor)
C39  value 100nF  [C0402]  (hidden comment: Capacitor)
C40  value 100nF  [C0402]  (hidden comment: Capacitor)
C41  value 100nF  [C0402]  (hidden comment: Capacitor)
C42  value 100nF  [C0402]  (hidden comment: Capacitor)
C43  value 100nF  [C0402]  (hidden comment: Capacitor)
C44  value 100nF  [C0402]  (hidden comment: Capacitor)
C45  value 100nF  [C0402]  (hidden comment: Capacitor)
C46  value 100nF  [C0402]  (hidden comment: Capacitor)
C47  value 100nF  [C0402]  (hidden comment: Capacitor)
C48  value 100nF  [C0402]  (hidden comment: Capacitor)
C49  value 100nF  [C0402]  (hidden comment: Capacitor)
C50  value 100nF  [C0402]  (hidden comment: Capacitor)
C51  value 100nF  [C0402]  (hidden comment: Capacitor)
C52  value 100nF  [C0402]  (hidden comment: Capacitor)
C53  value 100nF  [C0402]  (hidden comment: Capacitor)
C54  value 2.2uF  [C0805]  (hidden comment: Capacitor)
C55  value 10uF  [C0603]  (hidden comment: Capacitor)
C56  value 2.2uF  [C0402]  (hidden comment: Capacitor)
C57  value 2.2uF  [C0402]  (hidden comment: Capacitor)
C58  value 100nF  [C0402]  (hidden comment: Capacitor)
C59  value 10uF  [C0603]  (hidden comment: Capacitor)
C60  value 100nF  [C0402]  (hidden comment: Capacitor)
C61  value 100nF  [C0402]  (hidden comment: Capacitor)
CN15  value USB_C_12401826E412A  [CON_USB-TYPEC_AMPHENOL_12401826E412A]  (hidden comment: USB_TYPE_C_Receptacle)
CN16  Header 4x1  [CON_SAMTEC_TSW-104-07-G-S]  (value not drawn)
D1  value BAT54KFILM  [DIO_SOD523_1A_2K]  (hidden comment: SCHOTTKY_1A_2K)
JP3  Jumper_Header 2x1  [CON_SAMTEC_TSW-102-07-G-S]  (value not drawn)
JP4  Jumper_Header 2x1  [CON_SAMTEC_TSW-102-07-G-S]  (value not drawn)
R2  value 100K  [R0402]  (hidden comment: Resistor)
R14  value 5K1  [R0402]  (hidden comment: Resistor)
R15  value 100K  [R0402]  (hidden comment: Resistor)
R16  value 100K  [R0402]  (hidden comment: Resistor)
R17  value 100K  [R0402]  (hidden comment: Resistor)
R18  value 100K  [R0402]  (hidden comment: Resistor)
R19  value 100K  [R0402]  (hidden comment: Resistor)
R20  value 100K  [R0402]  (hidden comment: Resistor)
R21  value 0R  [R0402]  (hidden comment: Resistor)
R22  value 100K  [R0402]  (hidden comment: Resistor)
R23  value 5K1  [R0402]  (hidden comment: Resistor)
R24  value 100K  [R0402]  (hidden comment: Resistor)
R25  value 100K  [R0402]  (hidden comment: Resistor)
R26  value 100K  [R0402]  (hidden comment: Resistor)
R27  value 100K  [R0402]  (hidden comment: Resistor)
R28  value 100K  [R0402]  (hidden comment: Resistor)
R29  value 0R  [R0402]  (hidden comment: Resistor)
R30  value 3K  [R0402]  (hidden comment: Resistor)
R31  value 10K  [R0402]  (hidden comment: Resistor)
R32  value 47R  [R0402]  (hidden comment: Resistor)
R33  value 10K  [R0402]  (hidden comment: Resistor)
R34  value 47R  [R0402]  (hidden comment: Resistor)
R35  value 47R  [R0402]  (hidden comment: Resistor)
R36  value 5K1  [R0402]  (hidden comment: Resistor)
R37  value 47R  [R0402]  (hidden comment: Resistor)
R38  value 10K  [R0402]  (hidden comment: Resistor)
R39  value 10K  [R0402]  (hidden comment: Resistor)
R40  value 3K  [R0402]  (hidden comment: Resistor)
R41  value 100K  [R0402]  (hidden comment: Resistor)
R42  value 5K1  [R0402]  (hidden comment: Resistor)
R43  value 1K8  [R0402]  (hidden comment: Resistor)
R44  value 1K3  [R0402]  (hidden comment: Resistor)
R45  value 3K9  [R0402]  (hidden comment: Resistor)
R46  value 100K  [R0402]  (hidden comment: Resistor)
R47  value 100K  [R0402]  (hidden comment: Resistor)
R52  value 100K  [R0402]  (hidden comment: Resistor)
R53  value 100K  [R0402]  (hidden comment: Resistor)
R55  value 0R  [R0402]  (hidden comment: Resistor)
R56  value 33R  [R0402]  (hidden comment: Resistor)
R57  value 0R  [R0402]  (hidden comment: Resistor)
R58  value 33R  [R0402]  (hidden comment: Resistor)
R59  value 100K  [R0402]  (hidden comment: Resistor)
R60  value 100K  [R0402]  (hidden comment: Resistor)
R61  value 100K  [R0402]  (hidden comment: Resistor)
R62  value 100K  [R0402]  (hidden comment: Resistor)
R63  value 100K  [R0402]  (hidden comment: Resistor)
R64  value 100K  [R0402]  (hidden comment: Resistor)
R65  value 100K  [R0402]  (hidden comment: Resistor)
R66  value 100K  [R0402]  (hidden comment: Resistor)
R67  value 100K  [R0402]  (hidden comment: Resistor)
TP1  Test Point  [TP_SMD_1MM]  (value not drawn)  (no BOM)
U5  value STM32F723IEK6  [ICC_UFBGA201_176+25_10X10_P065]  (hidden comment: STLINK-V3EC)  (parts A,B,C of 3)
U6  74AVC4TD245BQ  [ICC_DHVQFN16-EPAD_SOT763-1_2P5X3P5_H0P85_P050]
U7  value ESDA25P35-1U1M  [ESD_QFN1610_2N_1K_2A]  (hidden comment: ESD-TRANSIL)
U8  ECMF02-2AMX6  [ESD_QFN-6L_1P7X1P5_P050]
U9  74AVC4TD245BQ  [ICC_DHVQFN16-EPAD_SOT763-1_2P5X3P5_H0P85_P050]
U10  TPS259535DSG  [ICC_WSON8-EPAD_2X2_P050]
U11  ST730M33R  [ICC_SOT23-5L_H1P45]
U12  STMPS2151STR  [MOS_SOT23-5L]
U15  74AVC4TD245BQ  [ICC_DHVQFN16-EPAD_SOT763-1_2P5X3P5_H0P85_P050]
X1  value 24MHz  [CRY_NX2016SA_4P]  (hidden comment: XTAL_4_PINS)

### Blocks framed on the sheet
VOLTAGE LEVEL SHIFTER: C24 C25 C30 C31 C60 C61 R15-R19 R24-R28 R32 R34 R35 R37 R41 R59-R67 U6 U9 U15
5V_STLK OVERVOLTAGE AND OVERCURRENT PROTECTION: C34-C36 R40 R42-R46 U10
EXTERNAL DEBUGGER SELECTION: JP4 R47
STLINK POWER: C37-C53 C56 C57 U5
ST-LINK POWER (3V3/300mA): C54 C55 D1 U11
5V ST-LINK PROTECTION for Legacy: C58 C59 R52 R53 U12

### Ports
DBG_BOOTLOADER (bidir), JTCK/SWCLK (bidir), JTDI (bidir), JTDO/SWO (bidir), JTMS/SWDIO (bidir), NRST (bidir), STLK_LED (bidir), T_DBG_RST (bidir), T_PWR_LED (bidir), T_SWCLK (bidir), VCP1_T_RX (bidir), VCP1_T_TX (bidir), VCP2_T_CTS (bidir), VCP2_T_RTS (bidir), VCP2_T_RX (bidir), VCP2_T_TX (bidir)

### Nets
3V3_STLK: C24.2 C30.2 C37.1 C38.1 C39.1 C40.1 C41.1 C42.1 C43.1 C44.1 C45.1 C46.1 C47.1 C48.1 C49.1 C50.1 C51.1 C52.1 C53.1 C55.2 C60.2 CN16.1 JP4.1(COMMON) R2.1 R15.2 R16.2 R17.2 R24.1 R25.2 R26.2 R27.2 R39.2 R52.1 R61.2 R62.2 R63.2 R64.2 U5.C1(VBAT) U5.C5(VDD) U5.C6(PDR_ON) U5.C7(VDD) U5.C8(VDD) U5.C9(VDD) U5.F3(VDD) U5.G3(VDD) U5.G13(VDD) U5.H13(VDD) U5.J12(VDD) U5.J13(VDD) U5.K4(VDD) U5.N8(VDD) U5.N9(VDD) U5.N10(VDD) U5.P1(VREF+) U5.R1(VDDA) U6.1(VCCA) U6.2(DIR1) U9.1(VCCA) U9.2(DIR1) U9.7(DIR4) U9.15(DIR2) U11.1(VOUT) U15.1(VCCA) U15.2(DIR1) U15.7(DIR4)
5V: R36.2
5V_STLK: C34.2 C59.2 R40.1 U10.5(OUT) U10.6(QOD) U12.1(OUT)
GND: C23.2 C24.1 C25.2 C26.2 C27.2 C28.1 C29.2 C30.1 C31.2 C32.1 C33.1 C34.1 C35.1 C36.1 C37.2 C38.2 C39.2 C40.2 C41.2 C42.2 C43.2 C44.2 C45.2 C46.2 C47.2 C48.2 C49.2 C50.2 C51.2 C52.2 C53.2 C54.1 C55.1 C56.1 C57.1 C58.1 C59.1 C60.1 C61.2 CN15.A1(GND1) CN15.A12(GND2) CN15.B1(GND3) CN15.B12(GND4) CN15.SH1(Shield1) CN15.SH2(Shield2) CN15.SH3(Shield3) CN15.SH4(Shield4) CN16.3 JP3.2(NO) R14.2 R23.2 R30.2 R31.2 R38.2 R41.1 R42.1 R45.2 R46.1 R47.1 R53.1 R59.1 U5.D5(VSS) U5.D6(BOOT0) U5.D7(VSS) U5.D8(VSS) U5.D9(VSS) U5.F2(VSS) U5.F6(VSS) U5.F7(VSS) U5.F8(VSS) U5.F9(VSS) U5.F10(VSS) U5.F12(VSS) U5.G2(VSS) U5.G6(VSS) U5.G7(VSS) U5.G8(VSS) U5.G9(VSS) U5.G10(VSS) U5.G12(VSS) U5.H6(VSS) U5.H7(VSS) U5.H8(VSS) U5.H9(VSS) U5.H10(VSS) U5.H12(VSS) U5.J6(VSS) U5.J7(VSS) U5.J8(VSS) U5.J9(VSS) U5.J10(VSS) U5.K6(VSS) U5.K7(VSS) U5.K8(VSS) U5.K9(VSS) U5.K10(VSS) U5.L4(BYPASS-REG) U5.M1(VSSA) U5.M8(VSS) U5.M9(VSS) U5.N1(VREF-) U6.7(DIR4) U6.8(GND) U6.9(~{OE}) U6.10(DIR3) U6.15(DIR2) U6.17(EP) U7.2(GND) U8.3(GND) U9.8(GND) U9.17(EP) U10.8(GND) U10.9(EP) U11.2(GND) U12.2(GND) U15.8(GND) U15.9(~{OE}) U15.10(DIR3) U15.15(DIR2) U15.17(EP) X1.2 X1.4
V_TARGET: C25.1 C31.1 C61.1 R18.2 R19.2 R28.2 R33.2 R60.2 R65.2 R66.2 R67.2 U6.16(VCCB) U9.16(VCCB) U15.16(VCCB)
VBUS_STLK: C23.1 C35.2 C58.2 CN15.A4(VBUS1) CN15.A9(VBUS2) CN15.B4(VBUS3) CN15.B9(VBUS4) D1.1(A) U7.1(IO1) U10.3(IN) U10.4(IN) U12.5(IN)
DBG_BOOTLOADER: R60.1 U6.14(B1) ; port DBG_BOOTLOADER
HiZ_DBG_IF_EN: JP4.2(NO) R47.2 U9.9(~{OE})
JTCK/SWCLK: R34.2 U6.11(B4) ; port JTCK/SWCLK
JTDI: R37.2 ; port JTDI
JTDO/SWO: R18.1 U6.13(B2) ; port JTDO/SWO
JTMS/SWDIO: R35.2 ; port JTMS/SWDIO
NRST: R29.2 ; port NRST
STLK_LED: U5.D15(STLK_LED/PA10) ; port STLK_LED
STLK_OSC_IN: C28.2 U5.G1(OSC_IN/PH0) X1.1
STLK_OSC_OUT: C29.1 U5.H1(OSC_OUT/PH1) X1.3
STLK_SWCLK: CN16.2 U5.A14(STLK_SWCLK/PA14)
STLK_SWDIO: CN16.4 U5.A15(STLK_SWDIO/PA13)
STLK_UCPD_CC1_C: C26.1 R20.2 U5.M5(ADCx_IN13/PC3)
STLK_UCPD_CC2_C: C27.1 R22.2 U5.N5(ADCx_IN14/PC4)
STLK_USB_CN_N: CN15.A7(D-1) CN15.B7(D-2) U8.2(D-)
STLK_USB_CN_P: CN15.A6(D+1) CN15.B6(D+2) U8.1(D+)
STLK_USB_N: U5.R14(USB_DEV_HS_N/PB14) U8.5(D-)
STLK_USB_P: U5.R15(USB_DEV_HS_P/PB15) U8.6(D+)
STLK_VCP_RX: R55.1 U5.C10(STLK_VCP_RX/PG9)
STLK_VCP_TX: R56.1 U5.A7(STLK_VCP_TX/PG14)
SW_DIR: R41.2 U5.R3(T_SW_DIR/PA7) U9.10(DIR3)
T_DBG_BOOT: R59.2 U5.B3(GPIO3/PE6) U6.3(A1)
T_DBG_RST: R2.2 U5.B2(GPIO2/PE5) ; port T_DBG_RST
T_JRCLK: R17.1 U5.A10(T_JRCLK/PB3) U6.6(A4)
T_JTDI: R27.1 U5.L3(T_JTDI/PF8) U9.6(A4)
T_MCO: R21.1 U5.F15(T_MCO/PA8)
T_PWR_EN: R46.2 R53.2 U5.R5(T_PWR_EN/PB0) U10.2(EN/UVLO) U12.4(EN)
T_PWR_EXT: R36.1 R38.1 U5.R4(T_PWR_EXT/PB1)
T_PWR_INT: R40.2 R42.2 R52.2 U5.B13(T_PWR_INT/PC11) U12.3(~{FAULT})
T_PWR_LED: U5.H15(T_PWR_LED/PC6) ; port T_PWR_LED
T_PWR_SEL1: R43.2 U5.D10(T_PWR_SEL1/PD4)
T_PWR_SEL2: R44.2 U5.C11(T_PWR_SEL2/PD5)
T_SWCLK: R25.1 U5.M6(T_JCLK_OUT/PB2) U5.M11(T_SWCLK/PH6) U9.4(A2) ; port T_SWCLK
T_SWDIO: R26.1 U5.L2(T_JTMS/T_SWDIO_OUT/PF9) U5.N12(T_SWDIO_IN/PH7) U9.5(A3)
T_SWO: R15.1 U5.A6(T_JTDO/PB5) U5.D12(T_SWO/PD2) U6.4(A2)
T_VCC_AIN: R31.1 R33.1 U5.N3(T_VCC_AIN/PA0)
T_VCP1_RX: R16.1 R55.2 U6.5(A3)
T_VCP1_TX: R24.2 R56.2 U9.3(A1)
T_VCP2_CTS: R63.1 U5.N14(UART_CTS/PD11) U15.5(A3)
T_VCP2_RTS: R64.1 U5.N13(UART_RTS/PD12) U15.6(A4)
T_VCP2_RX: R57.2 R62.1 U15.4(A2)
T_VCP2_TX: R58.2 R61.1 U15.3(A1)
VCP1_T_RX: R32.2 ; port VCP1_T_RX
VCP1_T_TX: R19.1 U6.12(B3) ; port VCP1_T_TX
VCP2_T_CTS: R67.1 U15.11(B4) ; port VCP2_T_CTS
VCP2_T_RTS: R66.1 U15.12(B3) ; port VCP2_T_RTS
VCP2_T_RX: U15.14(B1) ; port VCP2_T_RX
VCP2_T_TX: R65.1 U15.13(B2) ; port VCP2_T_TX
NetC32_2: C32.2 JP3.1(COMMON) U5.J1(NRST)
NetC33_2: C33.2 U5.J14(V12_OTGPHY)
NetC36_2: C36.2 U10.1(dVdt)
NetC54_2: C54.2 D1.2(K) U11.3(VIN) U11.5(EN)
NetC56_2: C56.2 U5.M10(VCAP1)
NetC57_2: C57.2 U5.F13(VCAP2)
NetCN15_A5: CN15.A5(CC1) R14.1 R20.1
NetCN15_B5: CN15.B5(CC2) R22.1 R23.1
NetR21_2: R21.2 TP1.1
NetR28_1: R28.1 R35.1 U9.12(B3)
NetR29_1: R29.1 U5.P3(T_NRST/PA6)
NetR30_1: R30.1 U5.J15(REXT_OTGPHY)
NetR32_1: R32.1 U9.14(B1)
NetR34_1: R34.1 U9.13(B2)
NetR37_1: R37.1 U9.11(B4)
NetR39_1: R39.1 U5.D4(HW_TYP_0/PI4)
NetR43_1: R43.1 R44.1 R45.1 U10.7(ILM)
NetR57_1: R57.1 U5.R13(UART_RX/PB11)
NetR58_1: R58.1 U5.B14(UART_TX/PC10)

Not connected (* = marked no-connect by the designer): CN15 A2(TX1+)* A3(TX1-)* A8(SBU1)* A10(RX2-)* A11(RX2+)* B2(TX2+)* B3(TX2-)* B8(SBU2)* B10(RX1-)* B11(RX1+)*; U5 A2(GPIO0/PE2)* A5(I2C_SCL/PB8)* A9(SPI_NSS/PB4)* B1(GPIO1/PE4)* B4(I2C_SDA/PB9)* B15(CAN_TX/PA12)* C4(HW_TYP_1/PI5)* C15(CAN_RX/PA11)* E15(SPI_SCK/PA9)* K13(GNDDetect/PG5)* M3(SPI_MOSI/PC1)* M4(SPI_MISO/PC2)* N6(T_JNRST/PF13)*; U8 4(NC)*; U11 4(NC/ADJ)*

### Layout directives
differential pair; rule Impedance Constraint [Min = 85.00    Max = 95.00    ]: STLK_USB_N, STLK_USB_P

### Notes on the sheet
- ST-LINK USB CONNECTOR
- STLINK
- TARGET MCU
- (near U5) STLINK MCU
- (near CN16) Reserved
- (near CN16) 1
- 5V_STLK OVERCURRENT PROTECTION MANAGEMENT
- PowerDefault.SNK
- T_PWR_SEL2/PD5
- T_PWR_SEL1/PD4
- (current limit: 550mA)
- (current limit: 1.66A)
- (current limit: 3.2A)
- Power1.5.SNK
- Power3.0.SNK
- Hi-Z
- 0
- Hi-Z = IO set in high impedance
- (near R47) (1): NOT FITTED FOR DEBUG WITH INTERNAL STLINK (DEFAULT)
- (near R47) (1): FITTED FOR DEBUG WITH EXTERNAL DEBUGER
- (near R47) Or output STLINK IOs isolated (Hi-Z)

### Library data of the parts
C23 = MCD-00205: Capacitor, MLCC, 100pF, 50V, NPO, +/-5%, 0402, T=0.5mm; Part_Preference: Recommended; Manufacturer: YAGEO; Manufacturer_Part_Number: CC0402JRNPO9BN101; Component_Country_Of_Origin: China
C24 C25 C30-C32 C37-C53 C60 C61 = MCD-00006: as C62 on sheet Accessories
C26 C27 C36 = MCD-02198: as C12 on sheet Accessories
C28 C29 = MCD-01774: Capacitor, MLCC, 2.7pF, 50V, NPO, +/-0.1pF, 0402, T=0.5mm; Part_Preference: Recommended; Manufacturer: YAGEO; Manufacturer_Part_Number: CC0402BRNPO9BN2R7; Component_Country_Of_Origin: China
C33 C56 C57 = MCD-02606: Capacitor, MLCC, 2.2uF, 6.3V, X5R, +/-10%, 0402, T=0.5mm; Part_Preference: Recommended; Manufacturer: YAGEO; Manufacturer_Part_Number: CC0402KRX5R5BB225; Order_Code_RS: 1992205
C34 C55 = MCD-00099: Capacitor, MLCC, 10uF, 10V, X5R, +/-10%, 0603, T=0.8mm; Part_Preference: Recommended; Manufacturer: MURATA; Manufacturer_Part_Number: GRM188R61A106KE69D; Order_Code_RS: 170-6168; Component_Country_Of_Origin: Japan
C35 = MCD-02355: as C7 on sheet Extension_CN
C54 = MCD-02372: Capacitor, MLCC, 2.2uF, 25V, X7R, +/-10%, 0805, T=1,25mm; Manufacturer_Part_Number: GRM21BR71E225KE11L; Manufacturer: MURATA; Part_Preference: Recommended; ECCN_US: EAR99; ECCN_EU: NEC; Provided_By: SUBCO
C58 = MCD-02355: Capacitor, MLCC, 100nF, 25V, X7R, +/-10%, 0402, T=0.5mm; Part_Preference: Recommended; Manufacturer: WALSIN; Manufacturer_Part_Number: 0402B104K250CT; Order_Code_RS: 176-3114; Component_Country_Of_Origin: Unknown; ShowFields: YES; ID: 4461
C59 = MCD-00099: Capacitor, MLCC, 10uF, 10V, X5R, +/-10%, 0603, T=0.8mm; Part_Preference: Recommended; Manufacturer: MURATA; Manufacturer_Part_Number: GRM188R61A106KE69D; Order_Code_RS: 170-6168; Component_Country_Of_Origin: Japan; ShowFields: YES; ID: 2770
CN15 = MCD-03232: as CN9 on sheet Accessories
CN16 = MCD-00029: Header, 4x1, 2,54mm, VR, TH, Height 5.84mm/2.54mm; Manufacturer_Part_Number: TSW-104-07-x-S; Manufacturer: SAMTEC; Part_Type: Connector; Provided_By: SUBCO
D1 = MCD-01677: Small signal Schottky diodes; BMS_Part_Number: 9151123; Part_Type: Diode; Part_Preference: Recommended; Manufacturer: STMICROELECTRONICS; Manufacturer_HQ_COO: EU; Component_Country_Of_Origin: China; ShowFields: YES; ID: 3777
JP3 JP4 = MCD-00045: Header, 2x1, 2,54mm, VR, TH, Height 5.84mm/2.54mm; Part_Preference: Recommended; Part_Type: Connector; Manufacturer: SAMTEC; Manufacturer_Part_Number: TSW-102-07-G-S; Alternate_Manufacturer: JIUBABA; LIANYI; Alternate_Manufacturer_Part_Number: 313102S111116;313102S111116
R2 R15-R19 R24-R28 R41 R59-R67 = MCD-00059: Resistor,100K,0402,1%,1/16W; Manufacturer_Part_Number: RC0402FR-07100KL; Manufacturer: YAGEO; Alternate_Manufacturer_Part_Number: RT0402FRE07100KL; Provided_By: Subcon; Initial_Board_Reference: MB1274
R14 R23 R36 R42 = MCD-00333: Resistor, 5K1, 0402, +/-1%, 1/16W; Part_Preference: Recommended; Manufacturer: YAGEO; Manufacturer_Part_Number: RC0402FR-075K1L
R20 R22 R46 R47 R52 R53 = MCD-00059: Resistor, 100K, 0402, +/-1%, 1/16W; Part_Preference: Recommended; Manufacturer: YAGEO; Manufacturer_Part_Number: RC0402FR-07100KL; Component_Country_Of_Origin: China; ShowFields: YES; ID: 2533
R21 R29 R55 R57 = MCD-00052: Resistor, 0R, 0402, +/-5%, 1/16W; Part_Preference: Recommended; Manufacturer: YAGEO; Manufacturer_Part_Number: RC0402JR-070RL; Order_Code_RS: 618-5804; Component_Country_Of_Origin: China
R30 = MCD-00185: Resistor,3K,0402,1%,1/16W; Manufacturer_Part_Number: RC0402FR-073KL; Manufacturer: YAGEO; Provided_By: SUBCO
R31 R33 R38 R39 = MCD-00053: Resistor,10K,0402,1%,1/16W; Manufacturer_Part_Number: RC0402FR-0710KL; Manufacturer: YAGEO; Provided_By: SUBCO
R32 R34 R35 R37 = MCD-00481: Resistor,47R,0402,1%,1/16W; Manufacturer_Part_Number: RC0402FR-0747RL; Manufacturer: YAGEO; Provided_By: SUBCO; Initial_Board_Reference: MBxxxx
R40 = MCD-00185: Resistor, 3K, 0402, +/-1%, 1/16W; Part_Preference: Recommended; Manufacturer: YAGEO; Manufacturer_Part_Number: RC0402FR-073KL; Component_Country_Of_Origin: China
R43 = MCD-00409: Resistor, 1K8, 0402, +/-1%, 1/16W; Part_Preference: Recommended; Manufacturer: YAGEO; Manufacturer_Part_Number: RC0402FR-071K8L; Component_Country_Of_Origin: China
R44 = MCD-00381: Resistor, 1K3, 0402, +/-1%, 1/16W; Part_Preference: Recommended; Manufacturer: YAGEO; Manufacturer_Part_Number: RC0402FR-071K3L; Component_Country_Of_Origin: China; ShowFields: YES; ID: 2898
R45 = MCD-02455: Resistor, 3K9, 0402, +/-1%, 1/16W, +/-100ppm/°C; Part_Preference: Recommended; Manufacturer: YAGEO; Manufacturer_Part_Number: RC0402FR-073K9L; Order_Code_RS: 198-7783; Component_Country_Of_Origin: China; ShowFields: YES; ID: 4561
R56 R58 = MCD-00455: Resistor, 33R, 0402, +/-1%, 1/16W; Part_Preference: Recommended; Manufacturer: YAGEO; Manufacturer_Part_Number: RC0402FR-0733RL; Component_Country_Of_Origin: China; ShowFields: YES; ID: 2821
TP1 = MCD-00074: Test Point 1mm; Part_Type: Mechanical
U5 = MCD-02706: MCU, Arm Cortex-M7 32-bit MCU, 512KB Flash, 276KB RAM, With Crypto; BMS_Part_Number: 9175300; Part_Type: IC; Part_Preference: Recommended; Manufacturer: STMICROELECTRONICS; Order_Code_RS: 135-8241; ShowFields: YES; ID: 4812
U6 U9 U15 = MCD-01945: 4-bit dual supply translating transceiver with configurable voltage translation; 3-state; Part_Type: IC; Manufacturer_Part_Number: 74AVC4TD245BQ,115; Manufacturer: NEXPERIA; Part_Preference: Recommended
U7 = MCD-01207: High power Transient voltage suppressor:25V/35A EOS and ESD transients protection.; Part_Type: Diode; Manufacturer: STMICROELECTRONICS; BMS_Part_Number: 9179045; ECCN_US: EAR99; ECCN_EU: NEC; Provided_By: SUBCO with ST control
U8 = MCD-00649: Common mode filter with ESD protection for USB 2.0 interface; BMS_Part_Number: 9151138; Part_Type: Diode; Part_Preference: Recommended; Manufacturer: STMICROELECTRONICS; Manufacturer_HQ_COO: EU; Component_Country_Of_Origin: China; ShowFields: YES; ID: 3094
U10 = MCD-02532: eFuse with Fast Overvoltage Protection 2.7V to 18V 4A 34mOhm 8-Pin WSON; Part_Type: IC; Part_Preference: Recommended; Manufacturer: TEXAS INSTRUMENTS; Order_Code_RS: NA
U11 = MCD-02514: LDO, 3.3V, 300mA, High input voltage: 2.5V to 28V, SOT23-5L; Part_Type: IC; Part_Preference: Recommended; Manufacturer: STMICROELECTRONICS
U12 = MCD-00159: 500mA, Enhanced single channel power switches with active high enable pin; BMS_Part_Number: 9159009; Part_Type: IC; Part_Preference: Recommended; Manufacturer: STMICROELECTRONICS; Manufacturer_HQ_COO: EU; Component_Country_Of_Origin: Malaysia; ShowFields: YES; ID: 2708
X1 = MCD-01036: Crystal, 24MHz, 6pF, +/-20ppm, 80R, 2x1.6mm; BMS_Part_Number: 9157045; Part_Type: Crystal_Osc; Part_Preference: Recommended; Manufacturer: NDK; Manufacturer_Part_Number: NX2016SA-24MHZ-EXS00A-CS10820; Component_Country_Of_Origin: Unknown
